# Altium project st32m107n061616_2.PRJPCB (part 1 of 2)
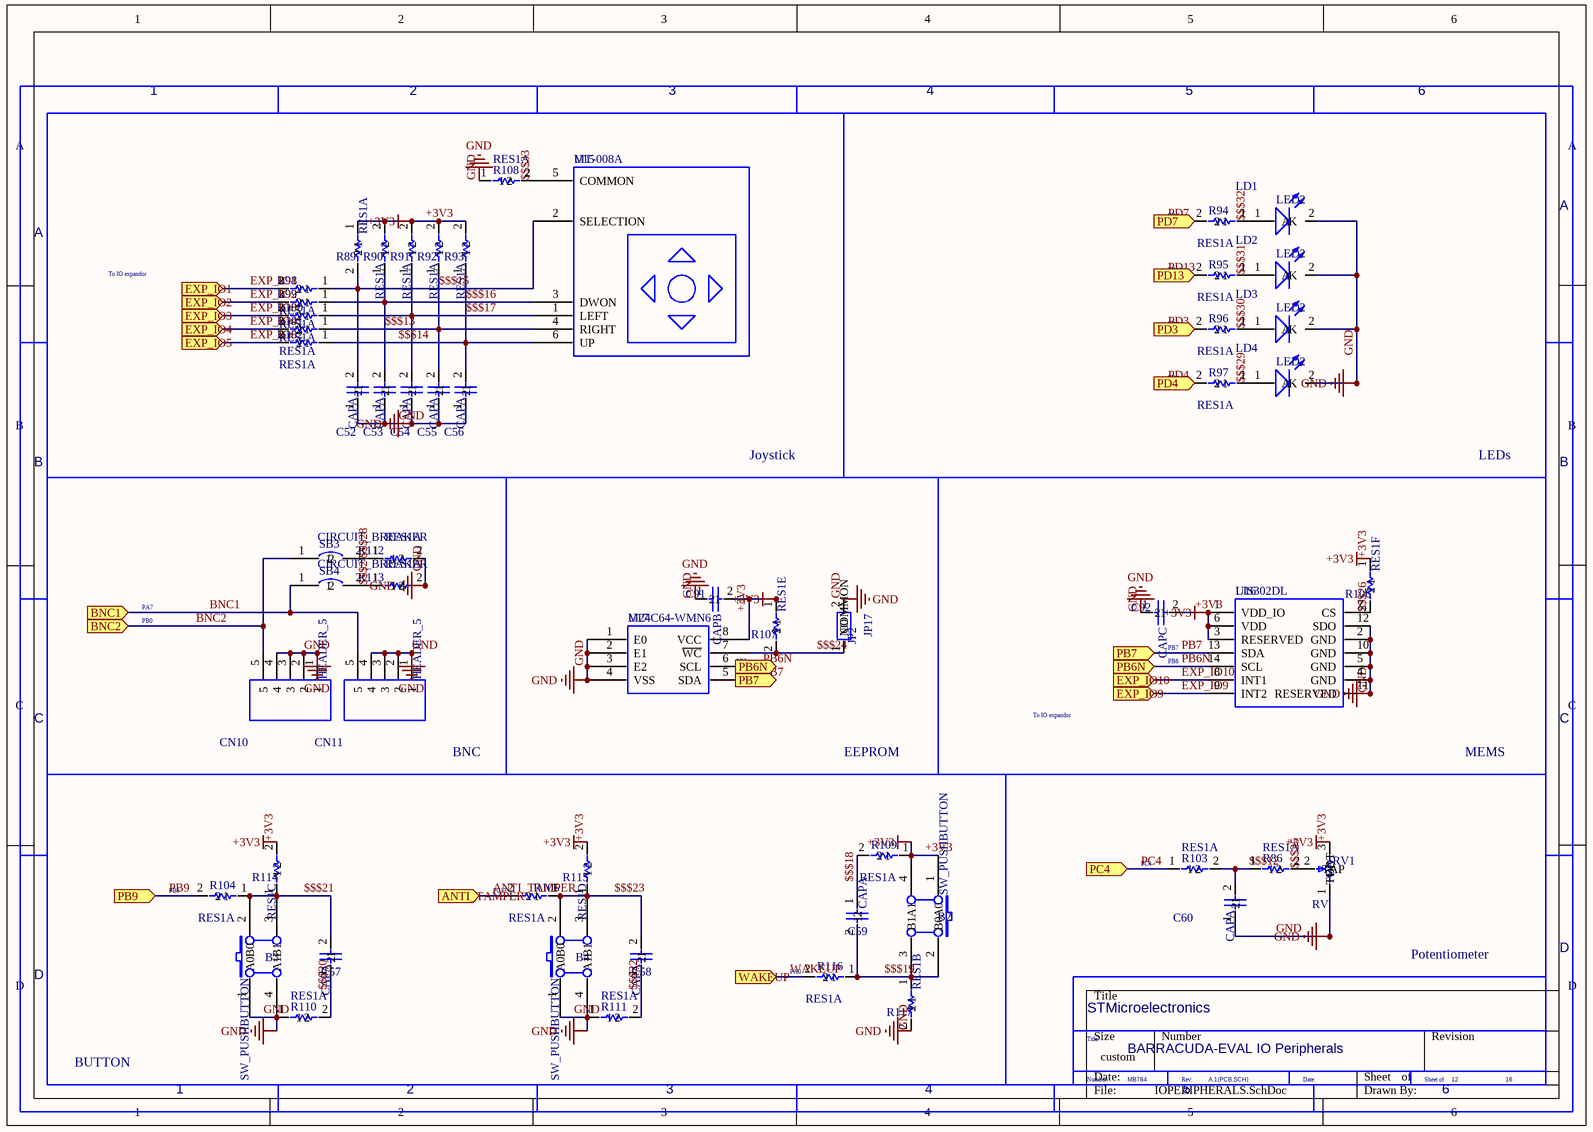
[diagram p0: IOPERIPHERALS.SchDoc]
17 sheets, 434 parts. Net scope: flat (ports and power ports of the same name join across sheets).
Sheets:
  IOPERIPHERALS.SchDoc
  EXTENSIONCONNECTOR.SchDoc
  IO_EXPANDOR.SchDoc
  JTAG&TRACE.SchDoc
  LCD.SchDoc
  MB784.SchDoc
  MCU.SchDoc
  MICROSDCARD.SchDoc
  MOTORCONTROL.SchDoc
  POWER.SchDoc
  SMARTCARD.SchDoc
  USART&IRDA.SchDoc
  USB_OTG_FS.SchDoc
  AUDIO.SchDoc
  CAN.SchDoc
  ETHERNET.SchDoc
  WIFIZGMD.SchDoc

## Sheet IOPERIPHERALS.SchDoc
size 297 x 210 mm

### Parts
B2  SW_PUSHBUTTON
B3  SW_PUSHBUTTON
B4  SW_PUSHBUTTON
C52  CAPA
C53  CAPA
C54  CAPA
C55  CAPA
C56  CAPA
C57  CAPA
C58  CAPA
C59  CAPA
C60  CAPA
C91  CAPB
C92  CAPC
CN10  HEADER_5
CN11  HEADER_5
JP17  JP2
LD1  LED2
LD2  LED2
LD3  LED2
LD4  LED2
R86  RES1A
R89  RES1A
R90  RES1A
R91  RES1A
R92  RES1A
R93  RES1A
R94  RES1A
R95  RES1A
R96  RES1A
R97  RES1A
R98  RES1A
R99  RES1A
R100  RES1A
R101  RES1A
R102  RES1A
R103  RES1A
R104  RES1A
R105  RES1A
R106  RES1F
R107  RES1E
R108  RES1A
R109  RES1A
R110  RES1A
R111  RES1A
R112  RES1A
R113  RES1A
R114  RES1C
R115  RES1D
R116  RES1A
R117  RES1B
RV1  RV
SB3  CIRCUIT_BREAKER
SB4  CIRCUIT_BREAKER
U15  MT-008A
U16  LIS302DL
U17  M24C64-WMN6

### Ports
ANTI_TAMPER, BNC1, BNC2, EXP_IO1, EXP_IO2, EXP_IO3, EXP_IO4, EXP_IO5, EXP_IO9, EXP_IO10, PB6N, PB7, PB9, PC4, PD3, PD4, PD7, PD13, WAKEUP

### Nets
+3V3: B2.1(A0) B2.4(A1) C91.2 C92.2 R89.1 R90.2 R91.2 R92.2 R93.2 R106.1 R107.1 R109.1 R114.2 R115.2 RV1.3(TOP) U16.1(VDD_IO) U16.3(RESERVED) U16.6(VDD) U17.8(VCC)
GND: B3.1(A0) B3.4(A1) B4.1(A0) B4.4(A1) C52.1 C53.1 C54.1 C55.1 C56.1 C60.1 C91.1 C92.1 CN10.1 CN10.2 CN10.3 CN10.4 CN11.1 CN11.2 CN11.3 CN11.4 JP17.2(NO) LD1.2(K) LD2.2(K) LD3.2(K) LD4.2(K) R108.1 R110.1 R111.1 R112.2 R113.2 R117.2 RV1.1(BOT) U16.2(GND) U16.4(GND) U16.5(GND) U16.10(GND) U16.11(RESERVED) U16.12(SDO) U17.1(E0) U17.2(E1) U17.3(E2) U17.4(VSS)  [project net $$$275]
$$$12: C60.2 R86.1 R103.2
$$$13: C52.2 C53.2 C54.2 C55.2 C56.2 R89.2 R90.1 R91.1 R92.1 R93.1 R98.1 R99.1 R100.1 R101.1 R102.1 U15.1(LEFT) U15.2(SELECTION) U15.3(DWON) U15.4(RIGHT) U15.6(UP)  [also labelled $$$14, $$$15, $$$16, $$$17]
$$$18: C59.1 R109.2
$$$19: B2.2(B0) B2.3(B1) C59.2 R116.1 R117.1
$$$20: C57.1 R110.2
$$$21: B3.2(B0) B3.3(B1) C57.2 R104.1 R114.1
$$$22: C58.1 R111.2
$$$23: B4.2(B0) B4.3(B1) C58.2 R105.1 R115.1
$$$24: JP17.1(COMMON) R107.2 U17.7(~{WC})
$$$25: R86.2 RV1.2(TAP)
$$$26: R106.2 U16.7(CS)
$$$27: R113.1 SB4.2
$$$28: R112.1 SB3.2
$$$29: LD4.1(A) R97.1
$$$30: LD3.1(A) R96.1
$$$31: LD2.1(A) R95.1
$$$32: LD1.1(A) R94.1
$$$33: R108.2 U15.5(COMMON)
ANTI_TAMPER: R105.2 ; port ANTI_TAMPER
BNC1: CN10.5 CN11.5 SB3.1 SB4.1 ; port BNC2, port BNC1  [also labelled BNC2]
EXP_IO1: R98.2 ; port EXP_IO1
EXP_IO2: R99.2 ; port EXP_IO2
EXP_IO3: R100.2 ; port EXP_IO3
EXP_IO4: R101.2 ; port EXP_IO4
EXP_IO5: R102.2 ; port EXP_IO5
EXP_IO9: U16.9(INT2) ; port EXP_IO9
EXP_IO10: U16.8(INT1) ; port EXP_IO10
PB6N: U16.14(SCL) U17.6(SCL) ; port PB6N
PB7: U16.13(SDA) U17.5(SDA) ; port PB7
PB9: R104.2 ; port PB9  [project net PB11]
PC4: R103.1 ; port PC4
PD3: R96.2 ; port PD3
PD4: R97.2 ; port PD4
PD7: R94.2 ; port PD7
PD13: R95.2 ; port PD13
WAKEUP: R116.2 ; port WAKEUP

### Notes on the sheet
- 1
- 2
- 3
- 4
- 5
- 6
- A
- To IO expandor
- (near R95) PD13
- (near R94) PD7
- (near R96) PD3
- (near R97) PD4
- B
- Joystick
- LEDs
- PA7
- PB0
- (near U17) PB7
- PB6
- (near C92) PB7
- C
- BNC
- EEPROM
- MEMS
- (near R103) PC4
- (near R104) PB9
- (near R105) PC13
- D
- (near R116) PA0
- STMicroelectronics
- Potentiometer
- BUTTON
- Number:
- Title:
- BARRACUDA-EVAL IO Peripherals
- MB784
- Rev:
- A.1(PCB.SCH)
- Date:
- Sheet of
- 12
- 16

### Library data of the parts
B2-B4 = SW_PUSHBUTTON: SE PUSHBUTTON; PCB DECAL: PB10
C52-C60 = CAPA: Capacitor; Value: 100pF; PCB DECAL: RAD-0.3
C91 = CAPB: Capacitor; PCB DECAL: 0603
C92 = CAPC: Capacitor; PCB DECAL: 0603
CN10 CN11 = HEADER_5: Header, 5-Pin; PCB DECAL: VB334
JP17 = JP2: PCB DECAL: SIP2
LD1-LD4 = LED2: Typical RED, GREEN, YELLOW, AMBER GaAs LED; PCB DECAL: D0603
R86 R89-R105 R108-R113 R116 = RES1A: Resistor; Value: 1K; PCB DECAL: AXIAL-0.3
R106 = RES1F: Resistor; Value: 1K; PCB DECAL: AXIAL-0.3
R107 = RES1E: Resistor; Value: 1K; PCB DECAL: AXIAL-0.3
R114 = RES1C: Resistor; Value: 1K; PCB DECAL: AXIAL-0.3
R115 = RES1D: Resistor; Value: 1K; PCB DECAL: AXIAL-0.3
R117 = RES1B: Resistor; Value: 1K; PCB DECAL: AXIAL-0.3
RV1 = RV: PCB DECAL: ADJRH
SB3 SB4 = CIRCUIT_BREAKER: Circuit Breaker; PCB DECAL: SPST-2
U15 = MT-008A: PCB DECAL: JOY
U17 = M24C64-WMN6: PCB DECAL: SO8

## Sheet EXTENSIONCONNECTOR.SchDoc
size 297 x 210 mm
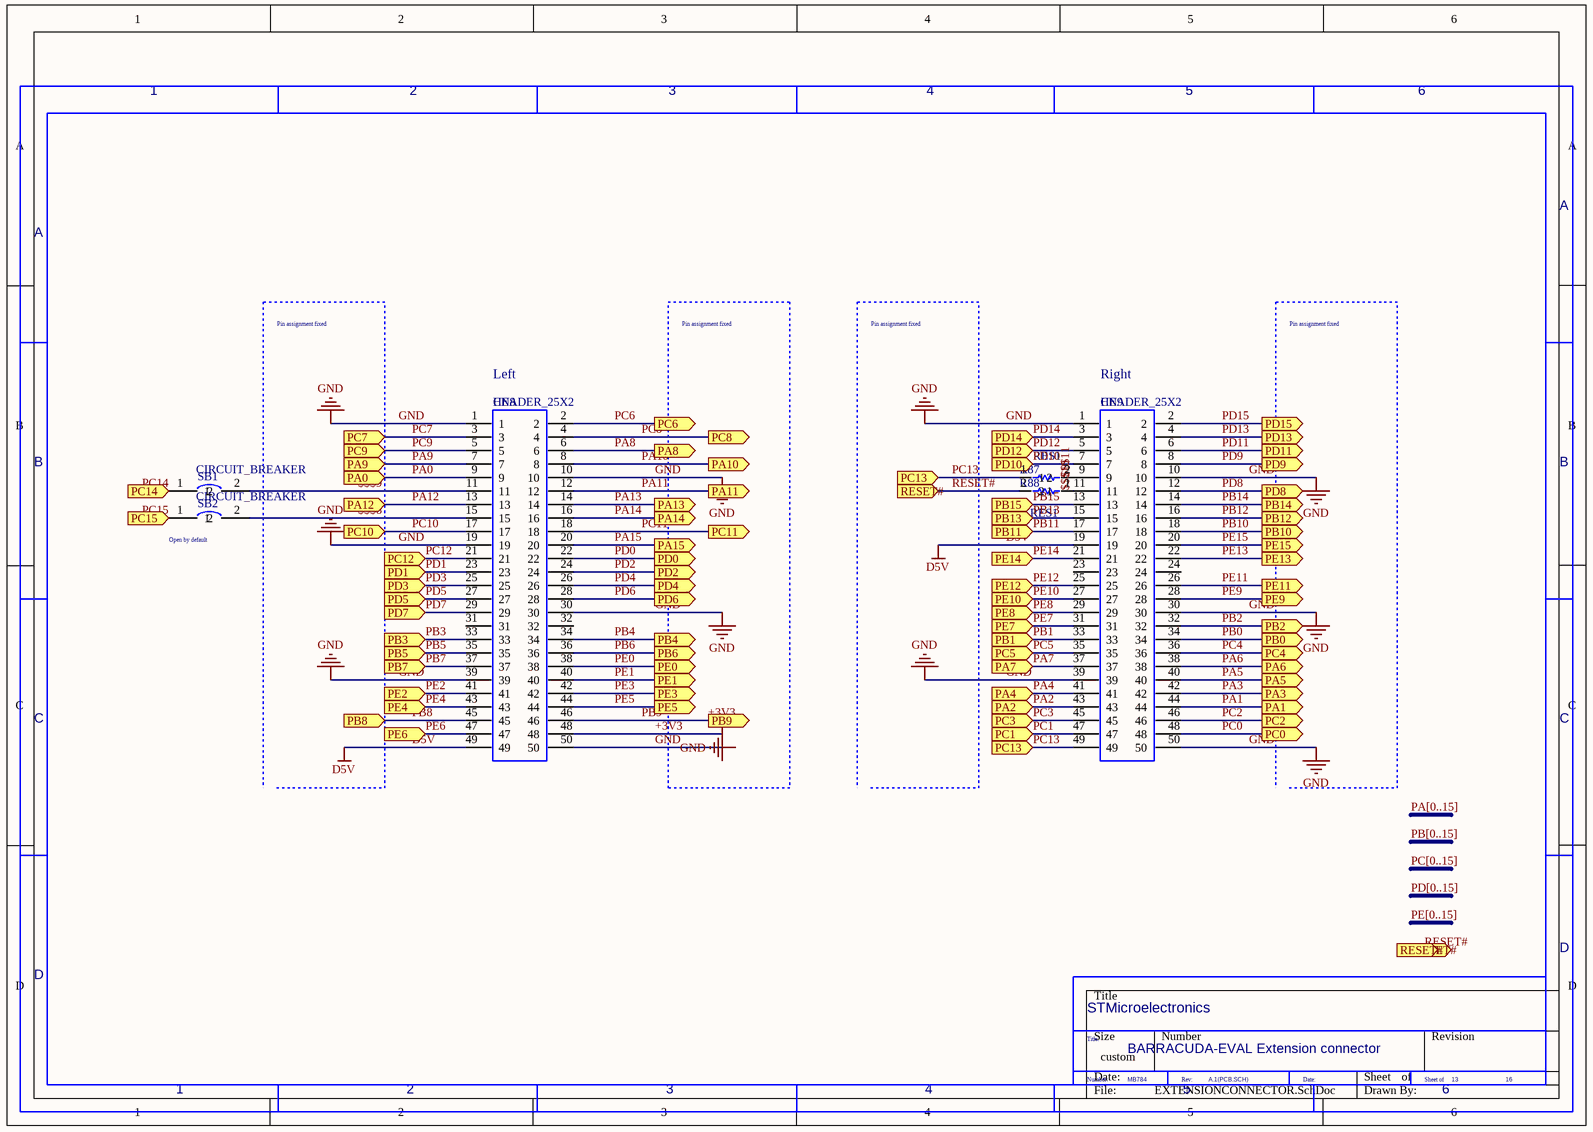
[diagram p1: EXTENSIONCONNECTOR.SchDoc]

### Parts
CN8  HEADER_25X2
CN9  HEADER_25X2
R87  RES1
R88  RES1
SB1  CIRCUIT_BREAKER
SB2  CIRCUIT_BREAKER

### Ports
PA0, PA1, PA2, PA3, PA4, PA5, PA6, PA7, PA8, PA9, PA10, PA11, PA12, PA13, PA14, PA15, PB0, PB1, PB2, PB3, PB4, PB5, PB6, PB7, PB8, PB9, PB10, PB11, PB12, PB13, PB14, PB15, PC0, PC1, PC2, PC3, PC4, PC5, PC6, PC7, PC8, PC9, PC10, PC11, PC12, PC13, PC14, PC15, PD0, PD1, PD2, PD3, PD4, PD5, PD6, PD7, PD8, PD9, PD10, PD11, PD12, PD13, PD14, PD15, PE0, PE1, PE2, PE3, PE4, PE5, PE6, PE7, PE8, PE9, PE10, PE11, PE12, PE13, PE14, PE15, RESET#

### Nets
+3V3: CN8.48
D5V: CN8.49 CN9.19
GND: CN8.1 CN8.10 CN8.13 CN8.14 CN8.19 CN8.30 CN8.39 CN8.50 CN9.1 CN9.10 CN9.30 CN9.39 CN9.50 ; port PA12, port PA13  [also labelled PA12, PA13]  [project net $$$275]
$$$8: CN8.15 SB2.2
$$$9: CN8.11 SB1.2
$$$10: CN9.11 R88.1
$$$11: CN9.9 R87.2
PA0: CN8.9 ; port PA0
PA1: CN9.44 ; port PA1
PA2: CN9.43 ; port PA2
PA3: CN9.42 ; port PA3
PA4: CN9.41 ; port PA4
PA5: CN9.40 ; port PA5
PA6: CN9.38 ; port PA6
PA7: CN9.37 ; port PA7
PA8: CN8.6 ; port PA8
PA9: CN8.7 ; port PA9
PA10: CN8.8 ; port PA10
PA11: CN8.12 ; port PA11
PA14: CN8.16 ; port PA14
PA15: CN8.20 ; port PA15
PB0: CN9.34 ; port PB0
PB1: CN9.33 ; port PB1
PB2: CN9.32 ; port PB2
PB3: CN8.33 ; port PB3
PB4: CN8.34 ; port PB4
PB6: CN8.36 ; port PB6
PB7: CN8.37 ; port PB7
PB8: CN8.45 ; port PB8
PB10: CN9.18 ; port PB10
PB11: CN8.35 CN8.46 CN9.17 ; port PB11, port PB5, port PB9  [also labelled PB5, PB9]
PB12: CN9.16 ; port PB12
PB13: CN9.15 ; port PB13
PB14: CN9.14 ; port PB14
PB15: CN9.13 ; port PB15
PC0: CN9.48 ; port PC0
PC1: CN9.47 ; port PC1
PC2: CN9.46 ; port PC2
PC3: CN9.45 ; port PC3
PC4: CN9.36 ; port PC4
PC5: CN9.35 ; port PC5
PC6: CN8.2 ; port PC6
PC7: CN8.3 ; port PC7
PC8: CN8.4 ; port PC8
PC9: CN8.5 ; port PC9
PC10: CN8.17 ; port PC10  [project net $$$17347]
PC11: CN8.18 ; port PC11
PC12: CN8.21 ; port PC12
PC13: CN9.49 R87.1 ; port PC13
PC14: SB1.1 ; port PC14
PC15: SB2.1 ; port PC15
PD0: CN8.22 ; port PD0
PD1: CN8.23 ; port PD1
PD2: CN8.24 ; port PD2  [project net BNC1]
PD3: CN8.25 ; port PD3
PD4: CN8.26 ; port PD4
PD5: CN8.27 ; port PD5
PD6: CN8.28 ; port PD6
PD7: CN8.29 ; port PD7
PD8: CN9.12 ; port PD8
PD9: CN9.8 ; port PD9
PD10: CN9.7 ; port PD10
PD11: CN9.6 ; port PD11
PD12: CN9.5 ; port PD12
PD13: CN9.4 ; port PD13
PD14: CN9.3 ; port PD14
PD15: CN9.2 ; port PD15
PE0: CN8.38 ; port PE0
PE1: CN8.40 ; port PE1
PE2: CN8.41 ; port PE2
PE3: CN8.42 ; port PE3
PE4: CN8.43 ; port PE4
PE5: CN8.44 ; port PE5
PE6: CN8.47 ; port PE6
PE7: CN9.31 ; port PE7
PE8: CN9.29 ; port PE8
PE9: CN9.28 ; port PE9
PE10: CN9.27 ; port PE10
PE11: CN9.26 ; port PE11
PE12: CN9.25 ; port PE12
PE13: CN9.22 ; port PE13
PE14: CN9.21 ; port PE14
PE15: CN9.20 ; port PE15
RESET#: R88.2 ; port RESET#

Not connected (* = marked no-connect by the designer): CN8 31 32; CN9 23 24

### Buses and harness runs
bus PA[0..15]
bus PB[0..15]
bus PC[0..15]
bus PD[0..15]
bus PE[0..15]

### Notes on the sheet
- 1
- 2
- 3
- 4
- 5
- 6
- A
- Pin assignment fixed
- (near CN8) Left
- (near CN9) Right
- B
- (near SB2) Open by default
- C
- D
- STMicroelectronics
- Number:
- Title:
- BARRACUDA-EVAL Extension connector
- MB784
- Rev:
- A.1(PCB.SCH)
- Date:
- Sheet of
- 13
- 16

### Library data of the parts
CN8 CN9 = HEADER_25X2: Header, 25-Pin, Dual row; PCB DECAL: 2*25P
R87 R88 = RES1: Resistor; Value: 1K; PCB DECAL: AXIAL-0.3
SB1 SB2 = CIRCUIT_BREAKER: Circuit Breaker; PCB DECAL: SPST-2

## Sheet IO_EXPANDOR.SchDoc
size 297 x 210 mm
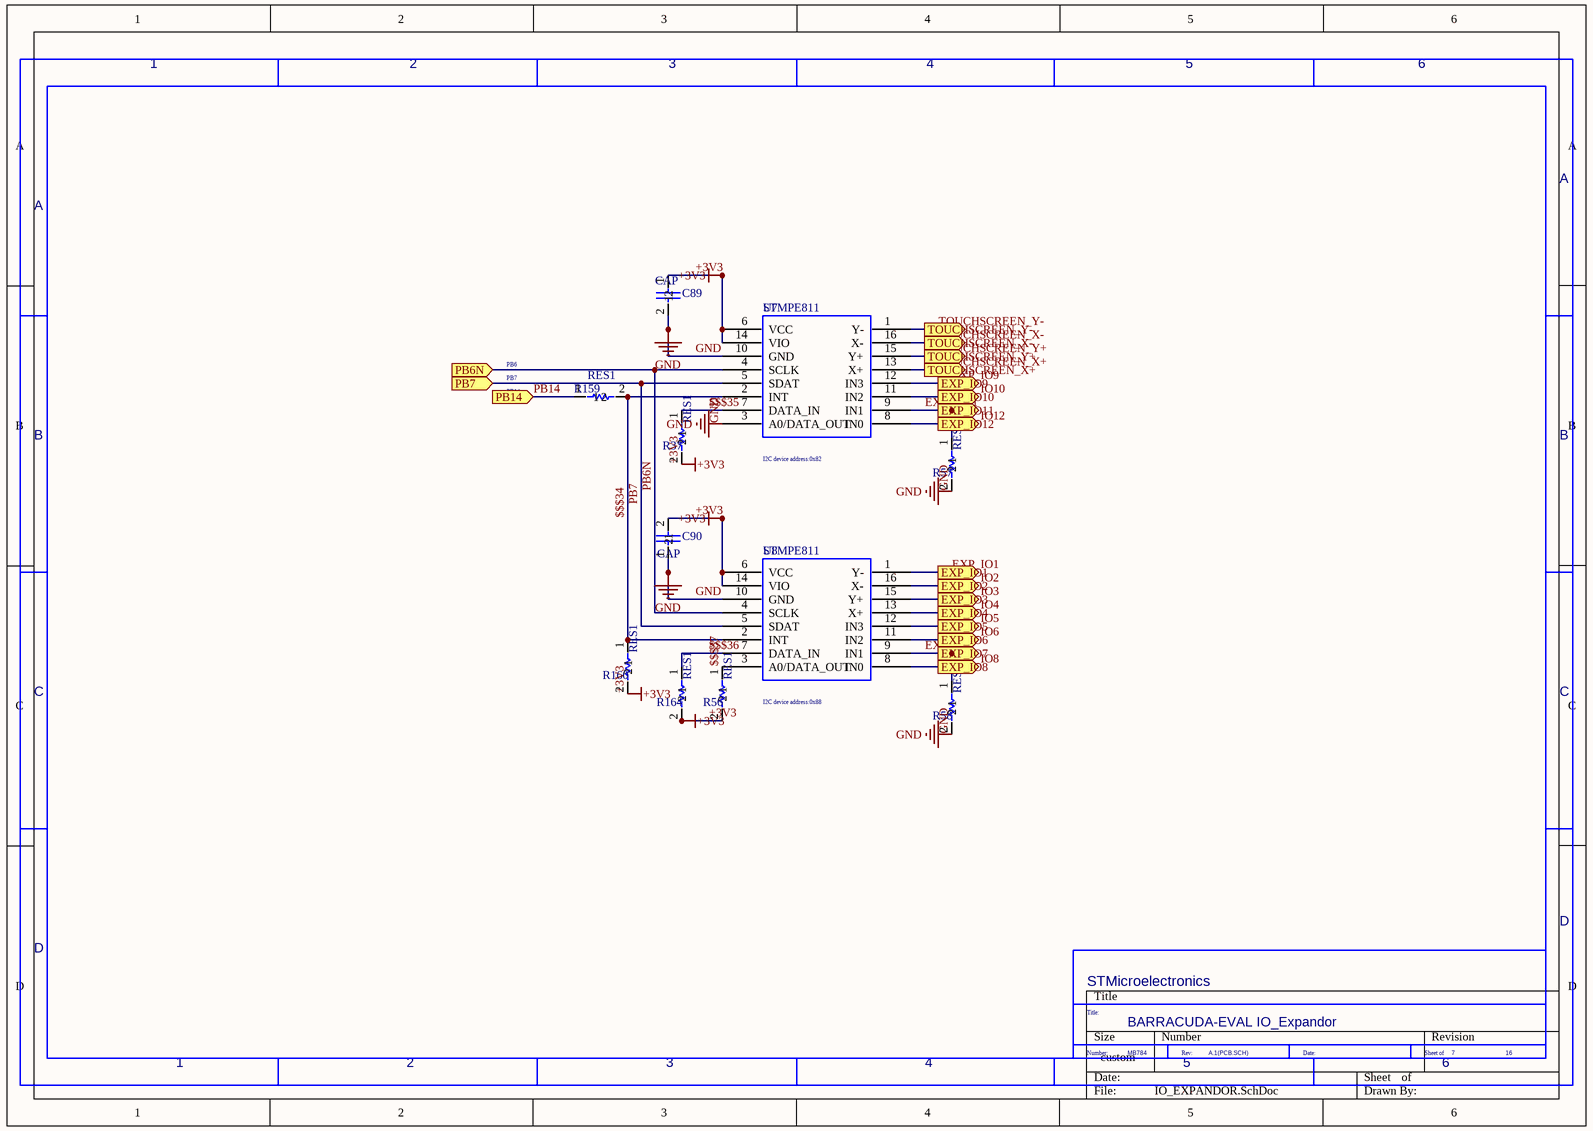
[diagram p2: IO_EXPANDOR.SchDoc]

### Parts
C89  CAP
C90  CAP
R37  RES1
R56  RES1
R57  RES1
R58  RES1
R159  RES1
R160  RES1
R164  RES1
U7  STMPE811
U8  STMPE811

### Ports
EXP_IO1, EXP_IO2, EXP_IO3, EXP_IO4, EXP_IO5, EXP_IO6, EXP_IO7, EXP_IO8, EXP_IO9, EXP_IO10, EXP_IO11, EXP_IO12, PB6N, PB7, PB14, TOUCHSCREEN_X+, TOUCHSCREEN_X-, TOUCHSCREEN_Y+, TOUCHSCREEN_Y-

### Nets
+3V3: C89.1 C90.2 R37.2 R56.2 R160.2 R164.2 U7.6(VCC) U7.14(VIO) U8.6(VCC) U8.14(VIO)
GND: C89.2 C90.1 R57.2 R58.2 U7.3(A0/DATA_OUT) U7.10(GND) U8.10(GND)  [project net $$$275]
$$$34: R159.2 R160.1 U7.2(INT) U8.2(INT)
$$$35: R37.1 U7.7(DATA_IN)
$$$36: R164.1 U8.7(DATA_IN)
$$$37: R56.1 U8.3(A0/DATA_OUT)
EXP_IO1: U8.1(Y-) ; port EXP_IO1
EXP_IO2: U8.16(X-) ; port EXP_IO2
EXP_IO3: U8.15(Y+) ; port EXP_IO3
EXP_IO4: U8.13(X+) ; port EXP_IO4
EXP_IO5: U8.12(IN3) ; port EXP_IO5
EXP_IO6: U8.11(IN2) ; port EXP_IO6
EXP_IO7: R58.1 U8.8(IN0) U8.9(IN1) ; port EXP_IO8, port EXP_IO7  [also labelled EXP_IO8]
EXP_IO9: U7.12(IN3) ; port EXP_IO9
EXP_IO10: U7.11(IN2) ; port EXP_IO10
EXP_IO11: R57.1 U7.8(IN0) U7.9(IN1) ; port EXP_IO12, port EXP_IO11  [also labelled EXP_IO12]
PB6N: U7.4(SCLK) U8.4(SCLK) ; port PB6N
PB7: U7.5(SDAT) U8.5(SDAT) ; port PB7
PB14: R159.1 ; port PB14
TOUCHSCREEN_X+: U7.13(X+) ; port TOUCHSCREEN_X+
TOUCHSCREEN_X-: U7.16(X-) ; port TOUCHSCREEN_X-
TOUCHSCREEN_Y+: U7.15(Y+) ; port TOUCHSCREEN_Y+
TOUCHSCREEN_Y-: U7.1(Y-) ; port TOUCHSCREEN_Y-

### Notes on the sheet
- 1
- 2
- 3
- 4
- 5
- 6
- A
- PB14
- PB7
- PB6
- B
- (near U7) I2C device address:0x82
- C
- I2C device address:0x88
- D
- Title:
- STMicroelectronics
- Number:
- BARRACUDA-EVAL IO_Expandor
- MB784
- Rev:
- A.1(PCB.SCH)
- Date:
- Sheet of
- 7
- 16

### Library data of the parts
C89 C90 = CAP: Capacitor; PCB DECAL: 0603
R37 R56-R58 R159 R160 R164 = RES1: as R87 on sheet EXTENSIONCONNECTOR
U7 U8 = STMPE811: PCB DECAL: QFN16

## Sheet JTAG&TRACE.SchDoc
size 297 x 210 mm
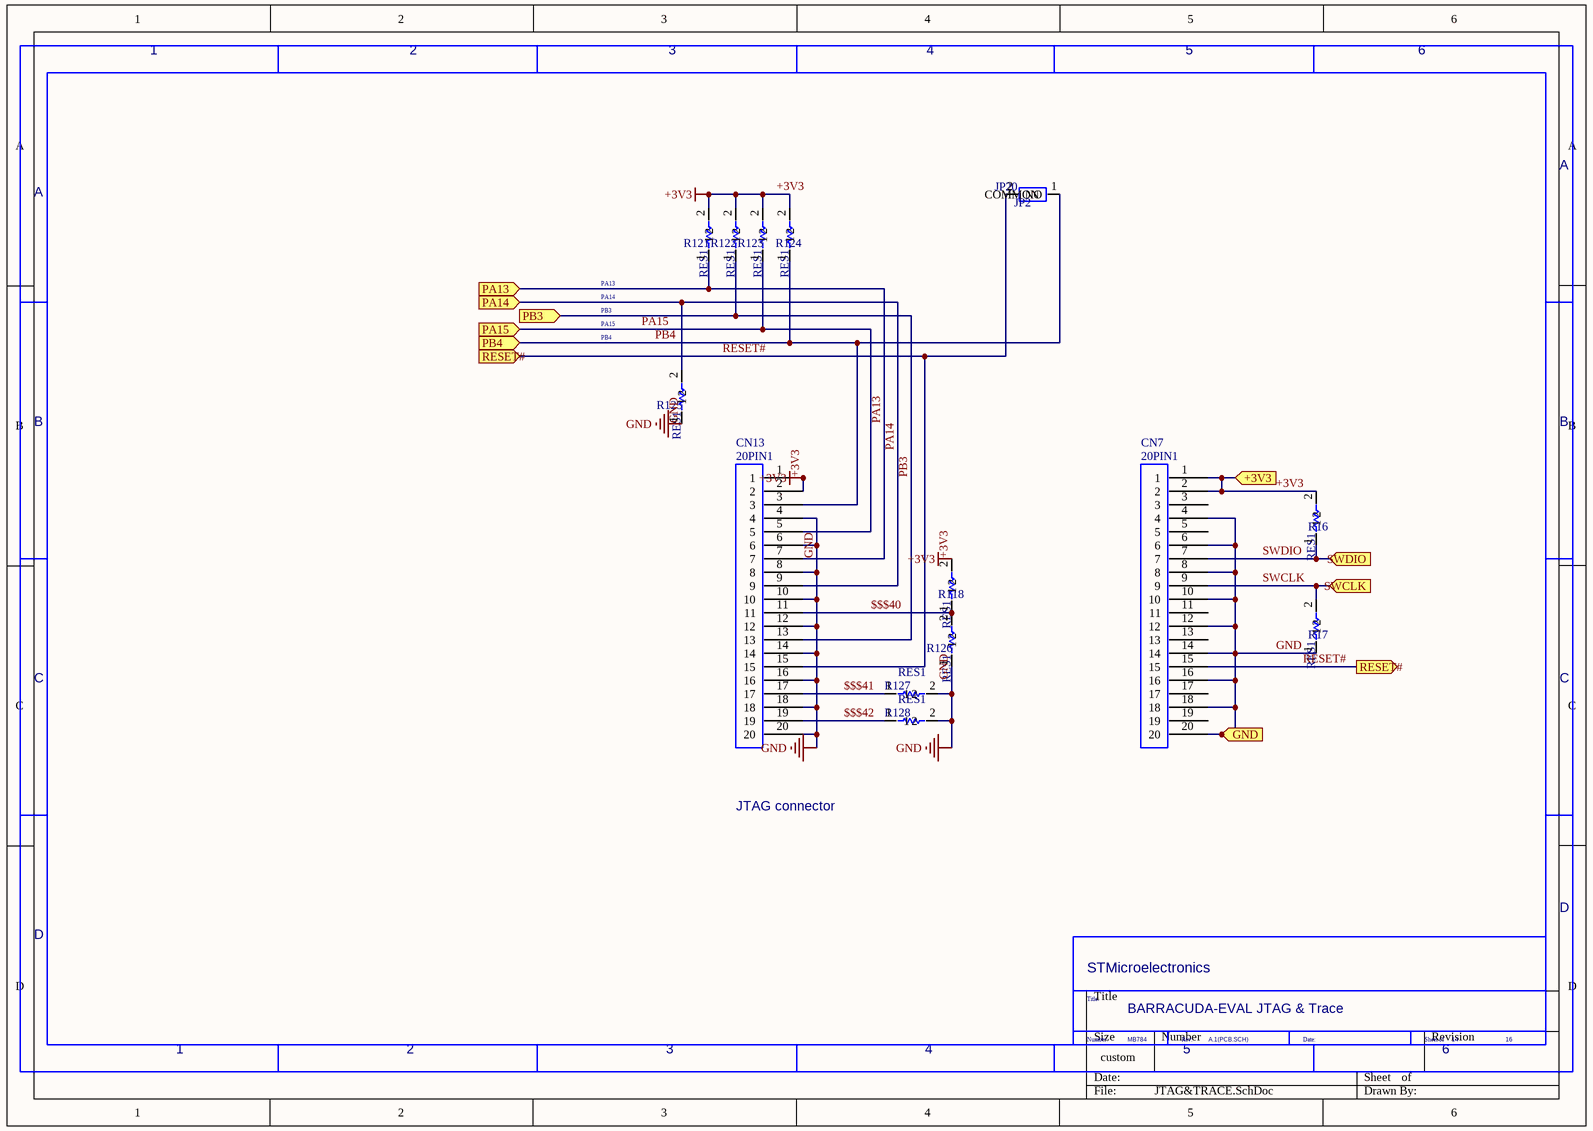
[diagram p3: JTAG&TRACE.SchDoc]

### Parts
CN7  20PIN1
CN13  20PIN1
JP20  JP2
R16  RES1
R17  RES1
R118  RES1
R121  RES1
R122  RES1
R123  RES1
R124  RES1
R125  RES1
R126  RES1
R127  RES1
R128  RES1

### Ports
+3V3, GND, PA13, PA14, PA15, PB3, PB4, RESET#, SWCLK, SWDIO

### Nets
+3V3: CN7.1 CN7.2 CN13.1 CN13.2 R16.2 R118.2 R121.2 R122.2 R123.2 R124.2 ; port +3V3
GND: CN7.4 CN7.6 CN7.8 CN7.10 CN7.12 CN7.14 CN7.16 CN7.18 CN7.20 CN13.4 CN13.6 CN13.7 CN13.8 CN13.10 CN13.12 CN13.14 CN13.16 CN13.18 CN13.20 R17.1 R121.1 R125.1 R126.1 R127.2 R128.2 ; port PA13, port GND  [also labelled PA13]  [project net $$$275]
$$$40: CN13.11 R118.1 R126.2
$$$41: CN13.17 R127.1
$$$42: CN13.19 R128.1
PA14: CN13.9 R125.2 ; port PA14
PA15: CN13.5 R123.1 ; port PA15
PB3: CN13.13 R122.1 ; port PB3
PB4: CN13.3 JP20.1(COMMON) R124.1 ; port PB4
RESET#: CN7.15 CN13.15 JP20.2(NO) ; port RESET#
SWCLK: CN7.9 R17.2 ; port SWCLK
SWDIO: CN7.7 R16.1 ; port SWDIO

Not connected (* = marked no-connect by the designer): CN7 3 5 11 13 17 19

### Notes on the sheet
- 1
- 2
- 3
- 4
- 5
- 6
- A
- PB4
- PA15
- PB3
- PA14
- PA13
- B
- C
- JTAG connector
- D
- Title:
- STMicroelectronics
- BARRACUDA-EVAL JTAG & Trace
- Number:
- MB784
- Rev:
- A.1(PCB.SCH)
- Date:
- Sheet of
- 14
- 16

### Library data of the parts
CN7 CN13 = 20PIN1: PCB DECAL: IDC20S
JP20 = JP2: PCB DECAL: SIP2
R16 R17 = RES1: Resistor; Value: 10K; PCB DECAL: AXIAL-0.3
R118 R121-R128 = RES1: as R87 on sheet EXTENSIONCONNECTOR

## Sheet LCD.SchDoc
size 297 x 210 mm
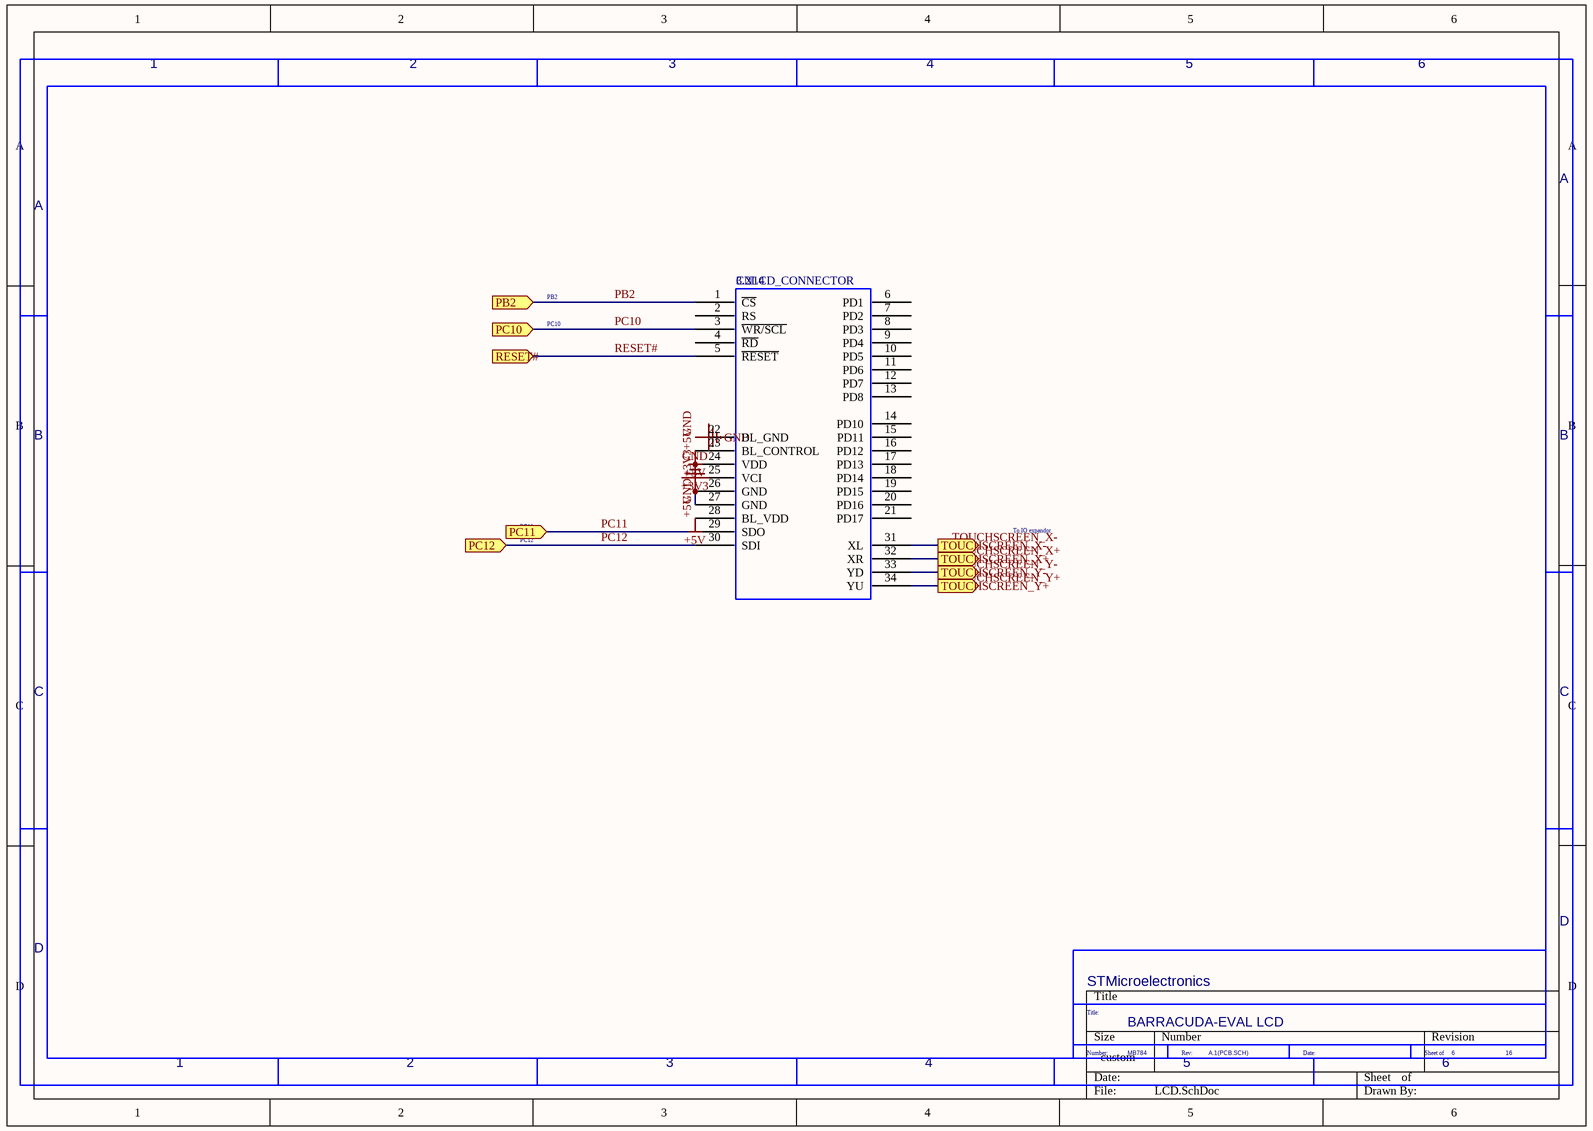
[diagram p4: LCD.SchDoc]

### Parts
CN14  3.2LCD_CONNECTOR

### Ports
PB2, PC10, PC11, PC12, RESET#, TOUCHSCREEN_X+, TOUCHSCREEN_X-, TOUCHSCREEN_Y+, TOUCHSCREEN_Y-

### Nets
+3V3: CN14.24(VDD) CN14.25(VCI)
+5V: CN14.23(BL_CONTROL) CN14.28(BL_VDD)
GND: CN14.22(BL_GND) CN14.26(GND) CN14.27(GND)  [project net $$$275]
PB2: CN14.1(~{CS}) ; port PB2
PC10: CN14.3(~{WR/SCL}) ; port PC10  [project net $$$17347]
PC11: CN14.29(SDO) ; port PC11
PC12: CN14.30(SDI) ; port PC12
RESET#: CN14.5(~{RESET}) ; port RESET#
TOUCHSCREEN_X+: CN14.32(XR) ; port TOUCHSCREEN_X+
TOUCHSCREEN_X-: CN14.31(XL) ; port TOUCHSCREEN_X-
TOUCHSCREEN_Y+: CN14.34(YU) ; port TOUCHSCREEN_Y+
TOUCHSCREEN_Y-: CN14.33(YD) ; port TOUCHSCREEN_Y-

Not connected (* = marked no-connect by the designer): CN14 2(RS) 4(~{RD}) 6(PD1) 7(PD2) 8(PD3) 9(PD4) 10(PD5) 11(PD6) 12(PD7) 13(PD8) 14(PD10) 15(PD11) 16(PD12) 17(PD13) 18(PD14) 19(PD15) 20(PD16) 21(PD17)

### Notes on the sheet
- 1
- 2
- 3
- 4
- 5
- 6
- A
- PC10
- PB2
- B
- PC12
- PC11
- To IO expandor
- C
- D
- Title:
- STMicroelectronics
- Number:
- BARRACUDA-EVAL LCD
- MB784
- Rev:
- A.1(PCB.SCH)
- Date:
- Sheet of
- 16

## Sheet MB784.SchDoc
size 297 x 210 mm

## Sheet MCU.SchDoc
size 297 x 210 mm
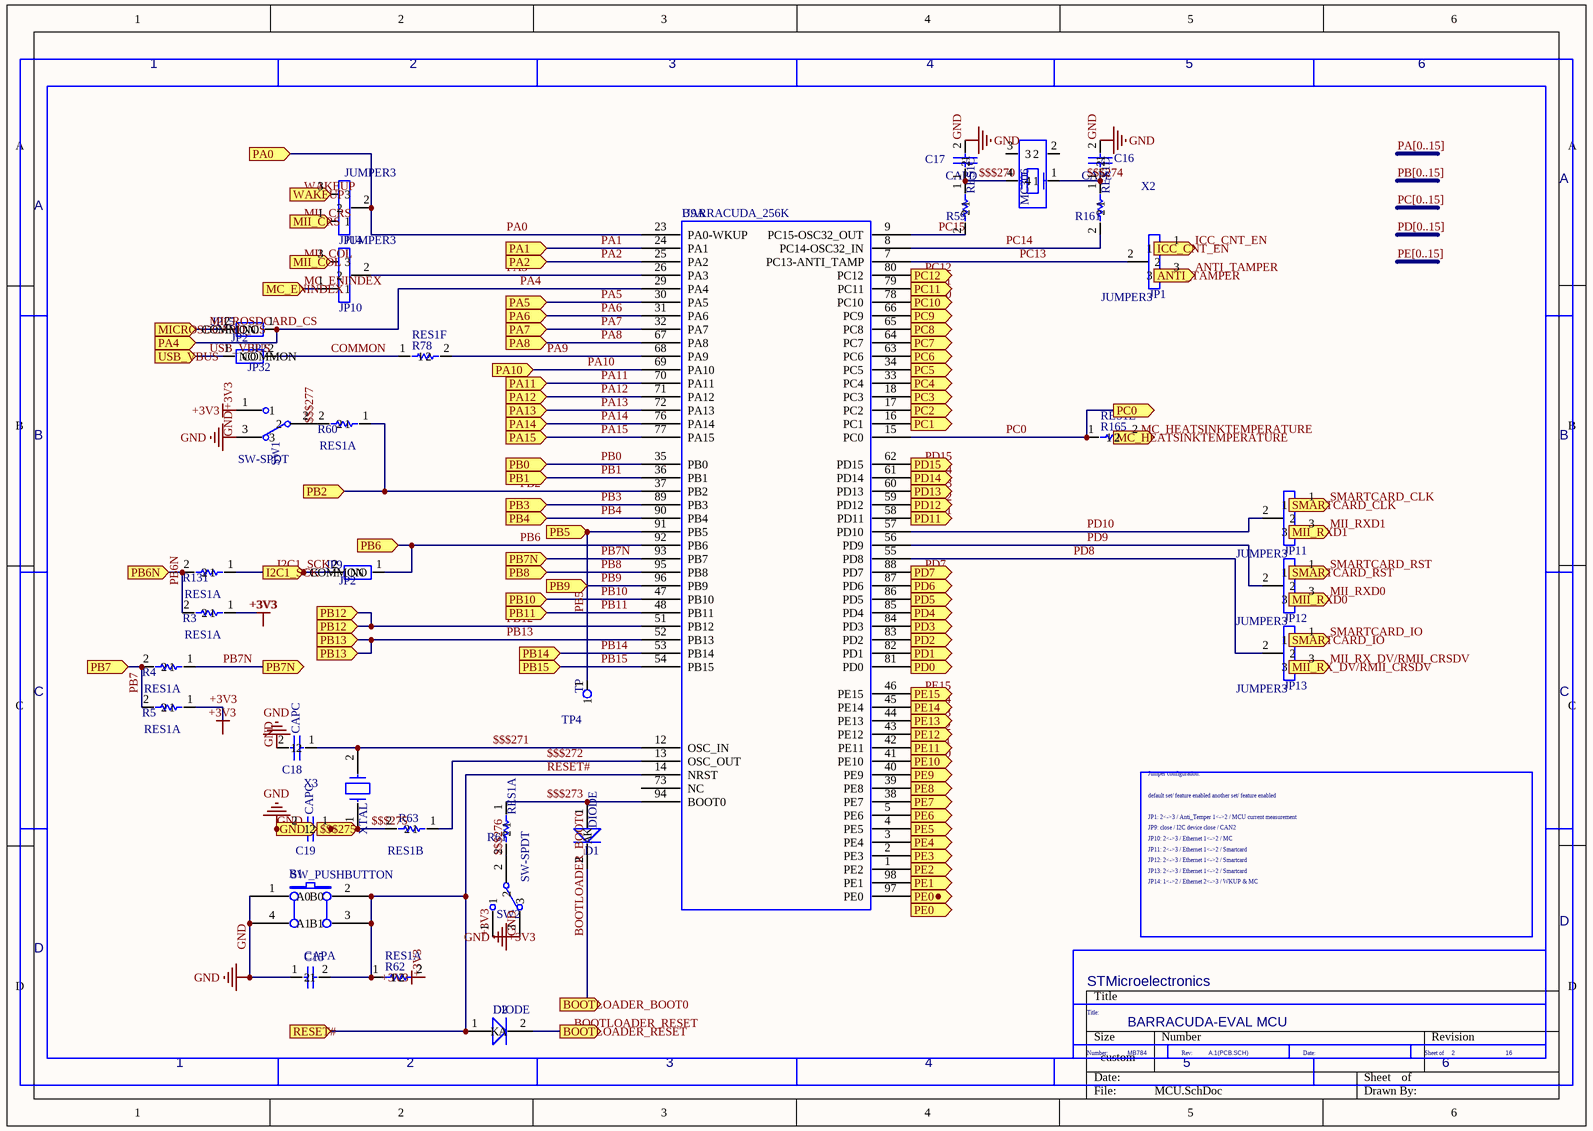
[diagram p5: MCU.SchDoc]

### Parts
B1  SW_PUSHBUTTON
C15  CAPA
C16  CAPE
C17  CAPD
C18  CAPC
C19  CAPC
D1  DIODE
D2  DIODE
JP1  JUMPER3
JP9  JP2
JP10  JUMPER3
JP11  JUMPER3
JP12  JUMPER3
JP13  JUMPER3
JP14  JUMPER3
JP15  JP2
JP32  JP2
R3  RES1A
R4  RES1A
R5  RES1A
R59  RES1C
R60  RES1A
R61  RES1A
R62  RES1A
R63  RES1B
R78  RES1F
R131  RES1A
R161  RES1D
R165  RES1E
SW1  SW-SPDT
SW2  SW-SPDT
TP4  TP
U9  BARRACUDA_256K  (part A of 2)
X2  MC306
X3  XTAL

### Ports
$$$275, ANTI_TAMPER, BOOTLOADER_BOOT0, BOOTLOADER_RESET, GND, I2C1_SCK, ICC_CNT_EN, MC_ENINDEX, MC_HEATSINKTEMPERATURE, MICROSDCARD_CS, MII_COL, MII_CRS, MII_RX_DV/RMII_CRSDV, MII_RXD0, MII_RXD1, PA0, PA1, PA2, PA4, PA5, PA6, PA7, PA8, PA10, PA11, PA12, PA13, PA14, PA15, PB0, PB1, PB2, PB3, PB4, PB5, PB6, PB6N, PB7, PB7N, PB8, PB9, PB10, PB11, PB12, PB13, PB14, PB15, PC0, PC1, PC2, PC3, PC4, PC5, PC6, PC7, PC8, PC9, PC10, PC11, PC12, PD0, PD1, PD2, PD3, PD4, PD5, PD6, PD7, PD11, PD12, PD13, PD14, PD15, PE0, PE1, PE2, PE3, PE4, PE5, PE6, PE7, PE8, PE9, PE10, PE11, PE12, PE13, PE14, PE15, RESET#, SMARTCARD_CLK, SMARTCARD_IO, SMARTCARD_RST, USB_VBUS, WAKEUP

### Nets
$$$275: B1.1(A0) B1.4(A1) C15.1 C16.2 C17.2 C18.2 C19.1 C19.2 R63.2 SW1.3 SW2.3 U9.71(PA12) U9.72(PA13) X3.1 ; port PA13, port PA12, port $$$275, port GND  [also labelled GND, PA12, PA13]
+3V3: R3.1 R5.1 R62.2 SW1.1 SW2.1
$$$270: C17.1 R59.1 X2.4
$$$271: C18.1 U9.12(OSC_IN) X3.2
$$$272: R63.1 U9.13(OSC_OUT)
$$$273: D1.1(A) R61.1 U9.94(BOOT0)
$$$274: C16.1 R161.1 X2.1
$$$276: R61.2 SW2.2
$$$277: R60.2 SW1.2
ANTI_TAMPER: JP1.3 ; port ANTI_TAMPER
BOOTLOADER_BOOT0: D1.2(K) ; port BOOTLOADER_BOOT0
BOOTLOADER_RESET: D2.2(K) ; port BOOTLOADER_RESET
COMMON: JP32.2(NO) R78.1
I2C1_SCK: JP9.2(NO) R131.1 ; port I2C1_SCK
ICC_CNT_EN: JP1.1 ; port ICC_CNT_EN
MC_ENINDEX: JP10.1 ; port MC_ENINDEX
MC_HEATSINKTEMPERATURE: R165.2 ; port MC_HEATSINKTEMPERATURE
MICROSDCARD_CS: JP15.2(NO) ; port MICROSDCARD_CS
MII_COL: JP10.3 ; port MII_COL
MII_CRS: JP14.1 ; port MII_CRS
MII_RX_DV/RMII_CRSDV: JP13.3 ; port MII_RX_DV/RMII_CRSDV
MII_RXD0: JP12.3 ; port MII_RXD0
MII_RXD1: JP11.3 ; port MII_RXD1
PA0: JP14.2 U9.23(PA0-WKUP) ; port PA0
PA1: U9.24(PA1) ; port PA1
PA2: U9.25(PA2) ; port PA2
PA3: JP10.2 U9.26(PA3)
PA4: JP15.1(COMMON) U9.29(PA4) ; port PA4
PA5: U9.30(PA5) ; port PA5
PA6: U9.31(PA6) ; port PA6
PA7: U9.32(PA7) ; port PA7
PA8: U9.67(PA8) ; port PA8
PA9: R78.2 U9.68(PA9)
PA10: U9.69(PA10) ; port PA10
PA11: U9.70(PA11) ; port PA11
PA14: U9.76(PA14) ; port PA14
PA15: U9.77(PA15) ; port PA15
PB0: U9.35(PB0) ; port PB0
PB1: U9.36(PB1) ; port PB1
PB2: R60.1 U9.37(PB2) ; port PB2
PB3: U9.89(PB3) ; port PB3
PB4: U9.90(PB4) ; port PB4
PB6: JP9.1(COMMON) U9.92(PB6) ; port PB6
PB6N: R3.2 R131.2 ; port PB6N
PB7: R4.2 R5.2 ; port PB7
PB7N: R4.1 U9.93(PB7) ; port PB7N
PB8: U9.95(PB8) ; port PB8
PB10: U9.47(PB10) ; port PB10
PB11: TP4.1 U9.48(PB11) U9.91(PB5) U9.96(PB9) ; port PB9, port PB5, port PB11  [also labelled PB5, PB9]
PB12: U9.51(PB12) ; port PB12
PB13: U9.52(PB13) ; port PB13
PB14: U9.53(PB14) ; port PB14
PB15: U9.54(PB15) ; port PB15
PC0: R165.1 U9.15(PC0) ; port PC0
PC1: U9.16(PC1) ; port PC1
PC2: U9.17(PC2) ; port PC2
PC3: U9.18(PC3) ; port PC3
PC4: U9.33(PC4) ; port PC4
PC5: U9.34(PC5) ; port PC5
PC6: U9.63(PC6) ; port PC6
PC7: U9.64(PC7) ; port PC7
PC8: U9.65(PC8) ; port PC8
PC9: U9.66(PC9) ; port PC9
PC10: U9.78(PC10) ; port PC10  [project net $$$17347]
PC11: U9.79(PC11) ; port PC11
PC12: U9.80(PC12) ; port PC12
PC13: JP1.2 U9.7(PC13-ANTI_TAMP)
PC14: R161.2 U9.8(PC14-OSC32_IN)
PC15: R59.2 U9.9(PC15-OSC32_OUT)
PD0: U9.81(PD0) ; port PD0
PD1: U9.82(PD1) ; port PD1
PD2: U9.83(PD2) ; port PD2  [project net BNC1]
PD3: U9.84(PD3) ; port PD3
PD4: U9.85(PD4) ; port PD4
PD5: U9.86(PD5) ; port PD5
PD6: U9.87(PD6) ; port PD6
PD7: U9.88(PD7) ; port PD7
PD8: JP13.2 U9.55(PD8)
PD9: JP12.2 U9.56(PD9)
PD10: JP11.2 U9.57(PD10)
PD11: U9.58(PD11) ; port PD11
PD12: U9.59(PD12) ; port PD12
PD13: U9.60(PD13) ; port PD13
PD14: U9.61(PD14) ; port PD14
PD15: U9.62(PD15) ; port PD15
PE0: U9.97(PE0) ; port PE0
PE1: U9.98(PE1) ; port PE1
PE2: U9.1(PE2) ; port PE2
PE3: U9.2(PE3) ; port PE3
PE4: U9.3(PE4) ; port PE4
PE5: U9.4(PE5) ; port PE5
PE6: U9.5(PE6) ; port PE6
PE7: U9.38(PE7) ; port PE7
PE8: U9.39(PE8) ; port PE8
PE9: U9.40(PE9) ; port PE9
PE10: U9.41(PE10) ; port PE10
PE11: U9.42(PE11) ; port PE11
PE12: U9.43(PE12) ; port PE12
PE13: U9.44(PE13) ; port PE13
PE14: U9.45(PE14) ; port PE14
PE15: U9.46(PE15) ; port PE15
RESET#: B1.2(B0) B1.3(B1) C15.2 D2.1(A) R62.1 U9.14(NRST) ; port RESET#
SMARTCARD_CLK: JP11.1 ; port SMARTCARD_CLK
SMARTCARD_IO: JP13.1 ; port SMARTCARD_IO
SMARTCARD_RST: JP12.1 ; port SMARTCARD_RST
USB_VBUS: JP32.1(COMMON) ; port USB_VBUS
WAKEUP: JP14.3 ; port WAKEUP

Not connected (* = marked no-connect by the designer): U9 73(NC); X2 2 3

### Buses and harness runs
bus PA[0..15]
bus PB[0..15]
bus PC[0..15]
bus PD[0..15]
bus PE[0..15]

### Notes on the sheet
- 1
- 2
- 3
- 4
- 5
- 6
- A
- B
- C
- default set/ feature enabled another set/ feature enabled
- Jumper configuration:
- JP14: 1<->2 / Ethernet 2<->3 / WKUP & MC
- JP13: 2<->3 / Ethernet 1<->2 / Smartcard
- JP12: 2<->3 / Ethernet 1<->2 / Smartcard
- JP11: 2<->3 / Ethernet 1<->2 / Smartcard
- JP10: 2<->3 / Ethernet 1<->2 / MC
- JP9: close / I2C device close / CAN2
- JP1: 2<->3 / Anti_Temper 1<->2 / MCU current measurement
- D
- Title:
- STMicroelectronics
- Number:
- BARRACUDA-EVAL MCU
- MB784
- Rev:
- A.1(PCB.SCH)
- Date:
- Sheet of
- 16

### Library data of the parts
B1 = SW_PUSHBUTTON: SE PUSHBUTTON; PCB DECAL: PB10
C15 = CAPA: Capacitor; Value: 100pF; PCB DECAL: 0603P
C16 = CAPE: Capacitor; PCB DECAL: 0603
C17 = CAPD: Capacitor; PCB DECAL: 0603
C18 C19 = CAPC: Capacitor; PCB DECAL: 0603
D1 D2 = DIODE: Default Diode; Code - JEDEC: DO-214-AB; PCB DECAL: DSO-C2/X3.3
JP1 JP10-JP14 = JUMPER3: PCB DECAL: SIP3
JP9 JP15 JP32 = JP2: PCB DECAL: SIP2
R3 R5 = RES1A: Resistor; Value: 4K7; PCB DECAL: AXIAL-0.3
R4 R131 = RES1A: Resistor; Value: 0; PCB DECAL: AXIAL-0.3
R59 = RES1C: as R114 on sheet IOPERIPHERALS
R60 R61 = RES1A: as R86 on sheet IOPERIPHERALS
R62 = RES1A: Resistor; Value: 1K; PCB DECAL: 0603
R63 = RES1B: as R117 on sheet IOPERIPHERALS
R78 = RES1F: as R106 on sheet IOPERIPHERALS
R161 = RES1D: as R115 on sheet IOPERIPHERALS
R165 = RES1E: as R107 on sheet IOPERIPHERALS
SW1 SW2 = SW-SPDT: SPDT Subminiature Toggle Switch, Right Angle Mounting, Vertical Actuation; Revision 1: Jul-2002: Re-released for DXP Platform.; Revision 2: 17-Dec-2003: Schematic revised, PCB Footprint replaced.; PCB DECAL: SIP3
U9 = BARRACUDA_256K: PCB DECAL: TQFP100
X2 = MC306: PCB DECAL: SM8
X3 = XTAL: Crystal

## Sheet MICROSDCARD.SchDoc
size 297 x 210 mm
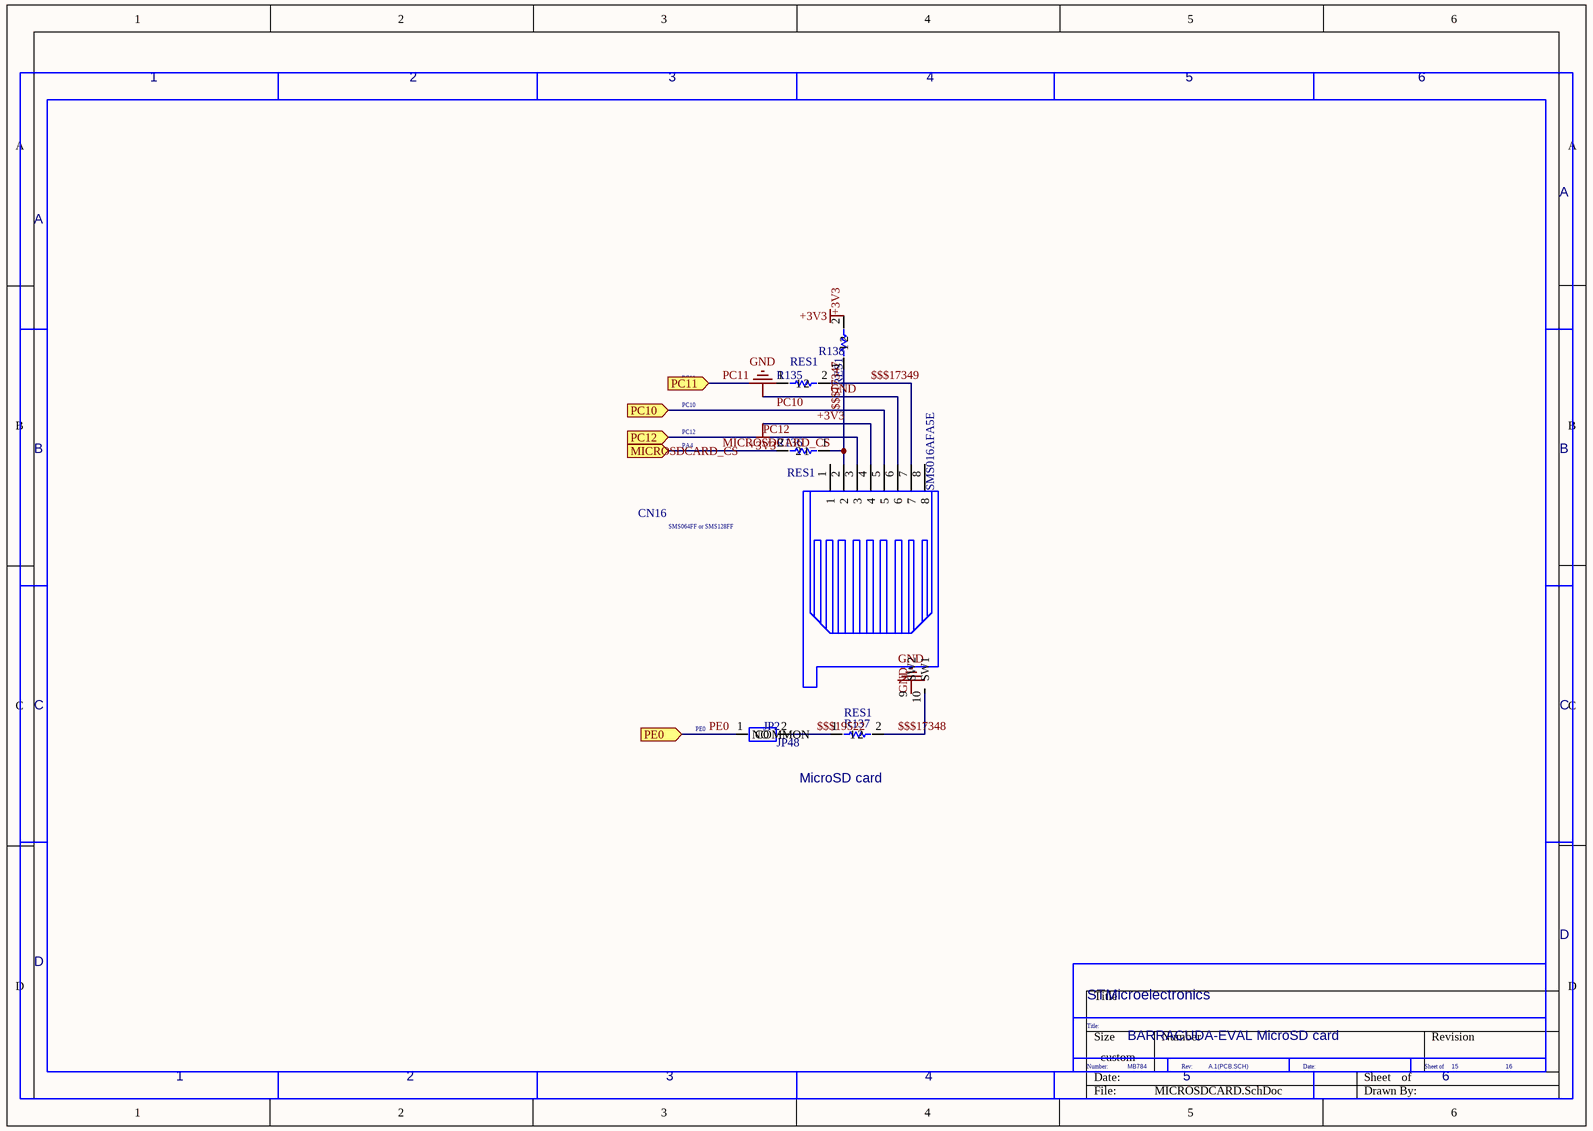
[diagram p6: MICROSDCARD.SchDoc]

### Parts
CN16  SMS016AFA5E
JP48  JP2
R135  RES1
R136  RES1
R137  RES1
R138  RES1

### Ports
MICROSDCARD_CS, PC10, PC11, PC12, PE0

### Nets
+3V3: CN16.4 R138.2
GND: CN16.6 CN16.9(SW2)  [project net $$$275]
$$$17347: CN16.2 CN16.5 R136.1 R138.1 ; port PC10  [also labelled PC10]
$$$17348: CN16.10(SW1) R137.2
$$$17349: CN16.7 R135.2
$$$19522: JP48.2(NO) R137.1
MICROSDCARD_CS: R136.2 ; port MICROSDCARD_CS
PC11: R135.1 ; port PC11
PC12: CN16.3 ; port PC12
PE0: JP48.1(COMMON) ; port PE0

Not connected (* = marked no-connect by the designer): CN16 1 8

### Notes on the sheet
- 1
- 2
- 3
- 4
- 5
- 6
- A
- PC10
- PC11
- B
- PA4
- PC12
- SMS064FF or SMS128FF
- C
- (near JP48) PE0
- MicroSD card
- D
- STMicroelectronics
- Number:
- Title:
- BARRACUDA-EVAL MicroSD card
- MB784
- Rev:
- A.1(PCB.SCH)
- Date:
- Sheet of
- 15
- 16

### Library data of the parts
CN16 = SMS016AFA5E: PCB DECAL: MSD(PJS008)
JP48 = JP2: PCB DECAL: SIP2
R135-R138 = RES1: as R87 on sheet EXTENSIONCONNECTOR

## Sheet MOTORCONTROL.SchDoc
size 297 x 210 mm
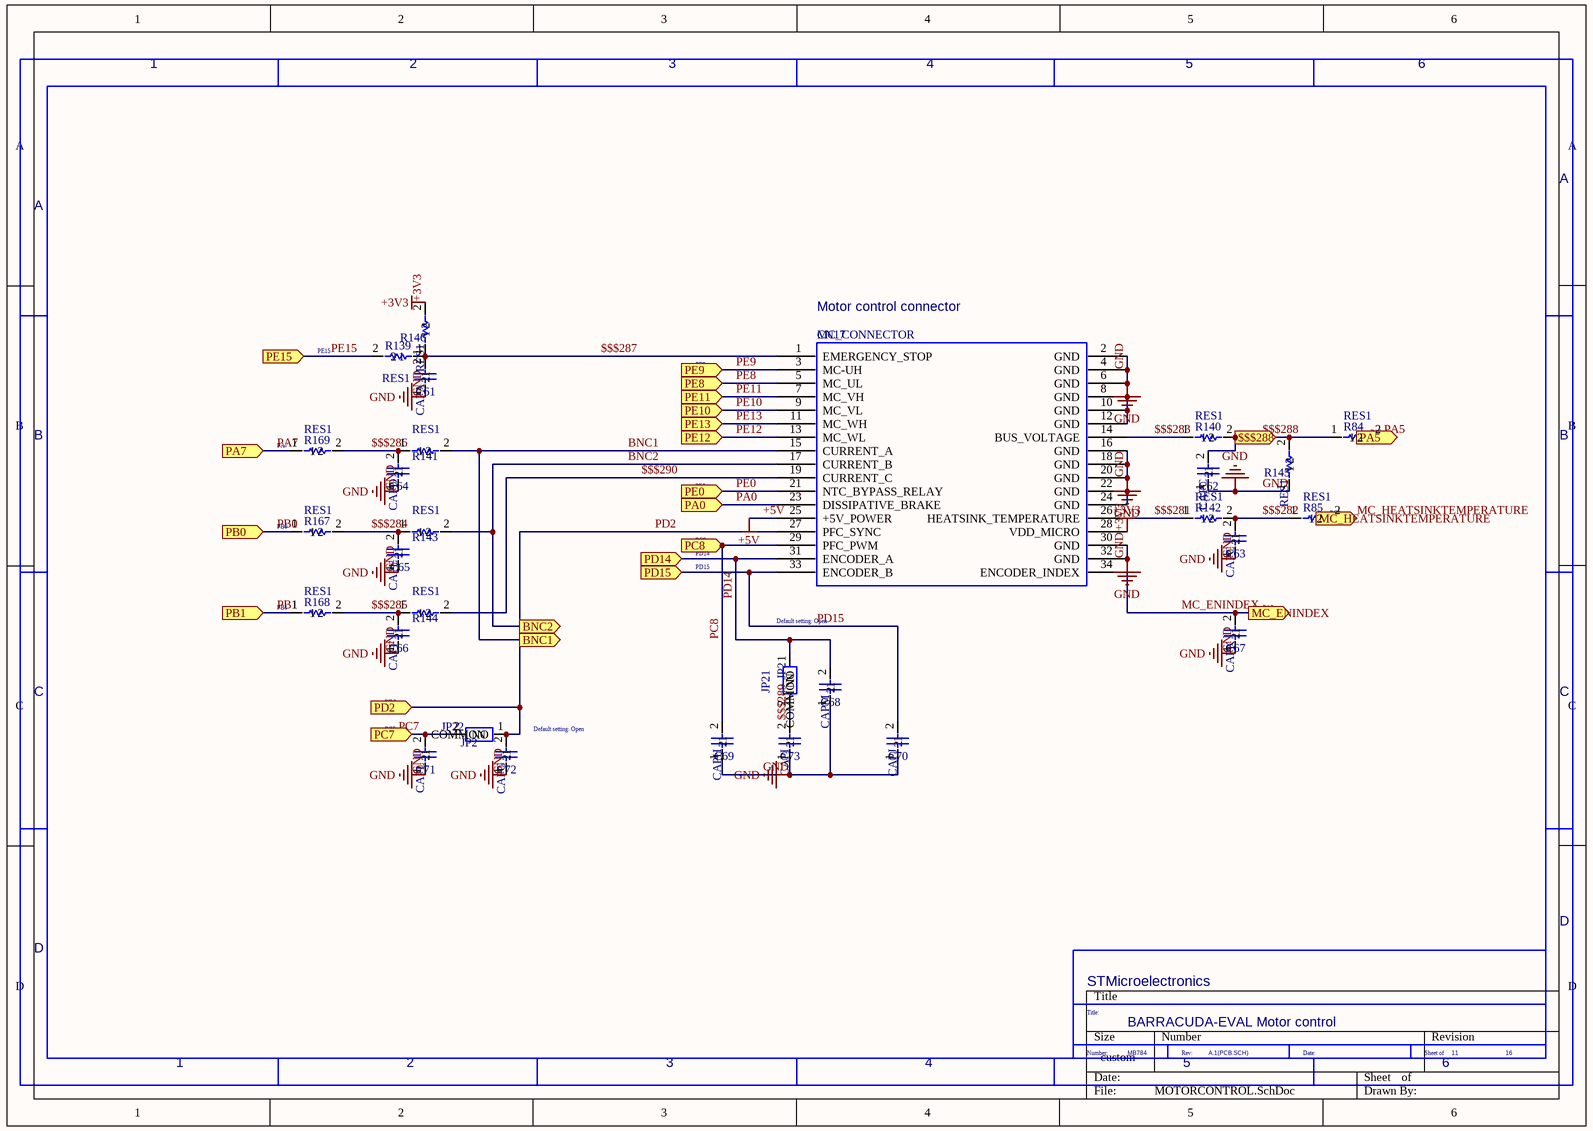
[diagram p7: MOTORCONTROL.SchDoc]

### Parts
C61  CAPA
C62  CAPC
C63  CAPC
C64  CAPD
C65  CAPE
C66  CAPF
C67  CAPK
C68  CAPM
C69  CAPH
C70  CAPJ
C71  CAPL
C72  CAPG
C73  CAPI
CN17  MC_CONNECTOR
JP21  JP2
JP22  JP2
R84  RES1
R85  RES1
R139  RES1
R140  RES1
R141  RES1
R142  RES1
R143  RES1
R144  RES1
R145  RES1
R146  RES1
R167  RES1
R168  RES1
R169  RES1

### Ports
$$$288, BNC1, BNC2, MC_ENINDEX, MC_HEATSINKTEMPERATURE, PA0, PA5, PA7, PB0, PB1, PC7, PC8, PD2, PD14, PD15, PE0, PE8, PE9, PE10, PE11, PE12, PE13, PE15

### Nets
+3V3: CN17.28(VDD_MICRO) R146.2
+5V: CN17.25(+5V_POWER)
GND: C61.1 C62.1 C63.1 C64.1 C65.1 C66.1 C67.1 C68.1 C69.1 C70.1 C71.1 C72.1 C73.1 CN17.2(GND) CN17.4(GND) CN17.6(GND) CN17.8(GND) CN17.10(GND) CN17.12(GND) CN17.16(GND) CN17.18(GND) CN17.20(GND) CN17.22(GND) CN17.24(GND) CN17.30(GND) CN17.32(GND) R145.1  [project net $$$275]
$$$281: CN17.26(HEATSINK_TEMPERATURE) R142.1
$$$282: C63.2 R85.1 R142.2
$$$283: CN17.14(BUS_VOLTAGE) R140.1
$$$284: C65.2 R143.1 R167.2
$$$285: C66.2 R144.1 R168.2
$$$286: C64.2 R141.1 R169.2
$$$287: C61.2 CN17.1(EMERGENCY_STOP) R139.1 R146.1
$$$288: C62.2 R84.1 R140.2 R145.2 ; port $$$288
$$$289: C73.2 JP21.2(NO)
$$$290: CN17.19(CURRENT_C) R144.2
BNC1: C72.2 CN17.15(CURRENT_A) CN17.17(CURRENT_B) CN17.27(PFC_SYNC) JP22.1(COMMON) R141.2 R143.2 ; port BNC2, port BNC1, port PD2  [also labelled BNC2, PD2]
MC_ENINDEX: C67.2 CN17.34(ENCODER_INDEX) ; port MC_ENINDEX
MC_HEATSINKTEMPERATURE: R85.2 ; port MC_HEATSINKTEMPERATURE
PA0: CN17.23(DISSIPATIVE_BRAKE) ; port PA0
PA5: R84.2 ; port PA5
PA7: R169.1 ; port PA7
PB0: R167.1 ; port PB0
PB1: R168.1 ; port PB1
PC7: C71.2 JP22.2(NO) ; port PC7
PC8: C69.2 CN17.29(PFC_PWM) ; port PC8
PD14: C68.2 CN17.31(ENCODER_A) JP21.1(COMMON) ; port PD14
PD15: C70.2 CN17.33(ENCODER_B) ; port PD15
PE0: CN17.21(NTC_BYPASS_RELAY) ; port PE0
PE8: CN17.5(MC_UL) ; port PE8
PE9: CN17.3(MC-UH) ; port PE9
PE10: CN17.9(MC_VL) ; port PE10
PE11: CN17.7(MC_VH) ; port PE11
PE12: CN17.13(MC_WL) ; port PE12
PE13: CN17.11(MC_WH) ; port PE13
PE15: R139.2 ; port PE15

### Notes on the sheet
- 1
- 2
- 3
- 4
- 5
- 6
- A
- (near CN17) Motor control connector
- PE15
- PE10
- PE11
- PE8
- PE9
- B
- (near R169) PA7
- PE12
- PE13
- (near R84) PA5
- (near R167) PB0
- PC8
- PA0
- PE0
- (near R85) PC0
- (near R168) PB1
- PD15
- PD14
- (near C67) PA3
- Default setting: Open
- C
- (near C71) PC7
- PD2
- D
- Title:
- STMicroelectronics
- Number:
- BARRACUDA-EVAL Motor control
- MB784
- Rev:
- A.1(PCB.SCH)
- Date:
- Sheet of
- 11
- 16

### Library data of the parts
C61 = CAPA: as C52 on sheet IOPERIPHERALS
C62 = CAPC: Capacitor; Value: 100pF; PCB DECAL: 0603C
C63 = CAPC: Capacitor; Value: 100pF; PCB DECAL: RAD-0.3
C64 = CAPD: Capacitor; Value: 100pF; PCB DECAL: RAD-0.3
C65 = CAPE: Capacitor; Value: 100pF; PCB DECAL: RAD-0.3
C66 = CAPF: Capacitor; Value: 100pF; PCB DECAL: RAD-0.3
C67 = CAPK: Capacitor; Value: 100pF; PCB DECAL: RAD-0.3
C68 = CAPM: Capacitor; Value: 100pF; PCB DECAL: RAD-0.3
C69 = CAPH: Capacitor; Value: 100pF; PCB DECAL: RAD-0.3
C70 = CAPJ: Capacitor; Value: 100pF; PCB DECAL: RAD-0.3
C71 = CAPL: Capacitor; Value: 100pF; PCB DECAL: RAD-0.3
C72 = CAPG: Capacitor; Value: 100pF; PCB DECAL: RAD-0.3
C73 = CAPI: Capacitor; Value: 100pF; PCB DECAL: RAD-0.3
CN17 = MC_CONNECTOR: PCB DECAL: IDC34S
JP21 JP22 = JP2: PCB DECAL: SIP2
R84 R85 R140-R145 R167-R169 = RES1: Resistor; Value: 1K; PCB DECAL: 0603
R139 R146 = RES1: as R87 on sheet EXTENSIONCONNECTOR

## Sheet POWER.SchDoc
size 297 x 210 mm
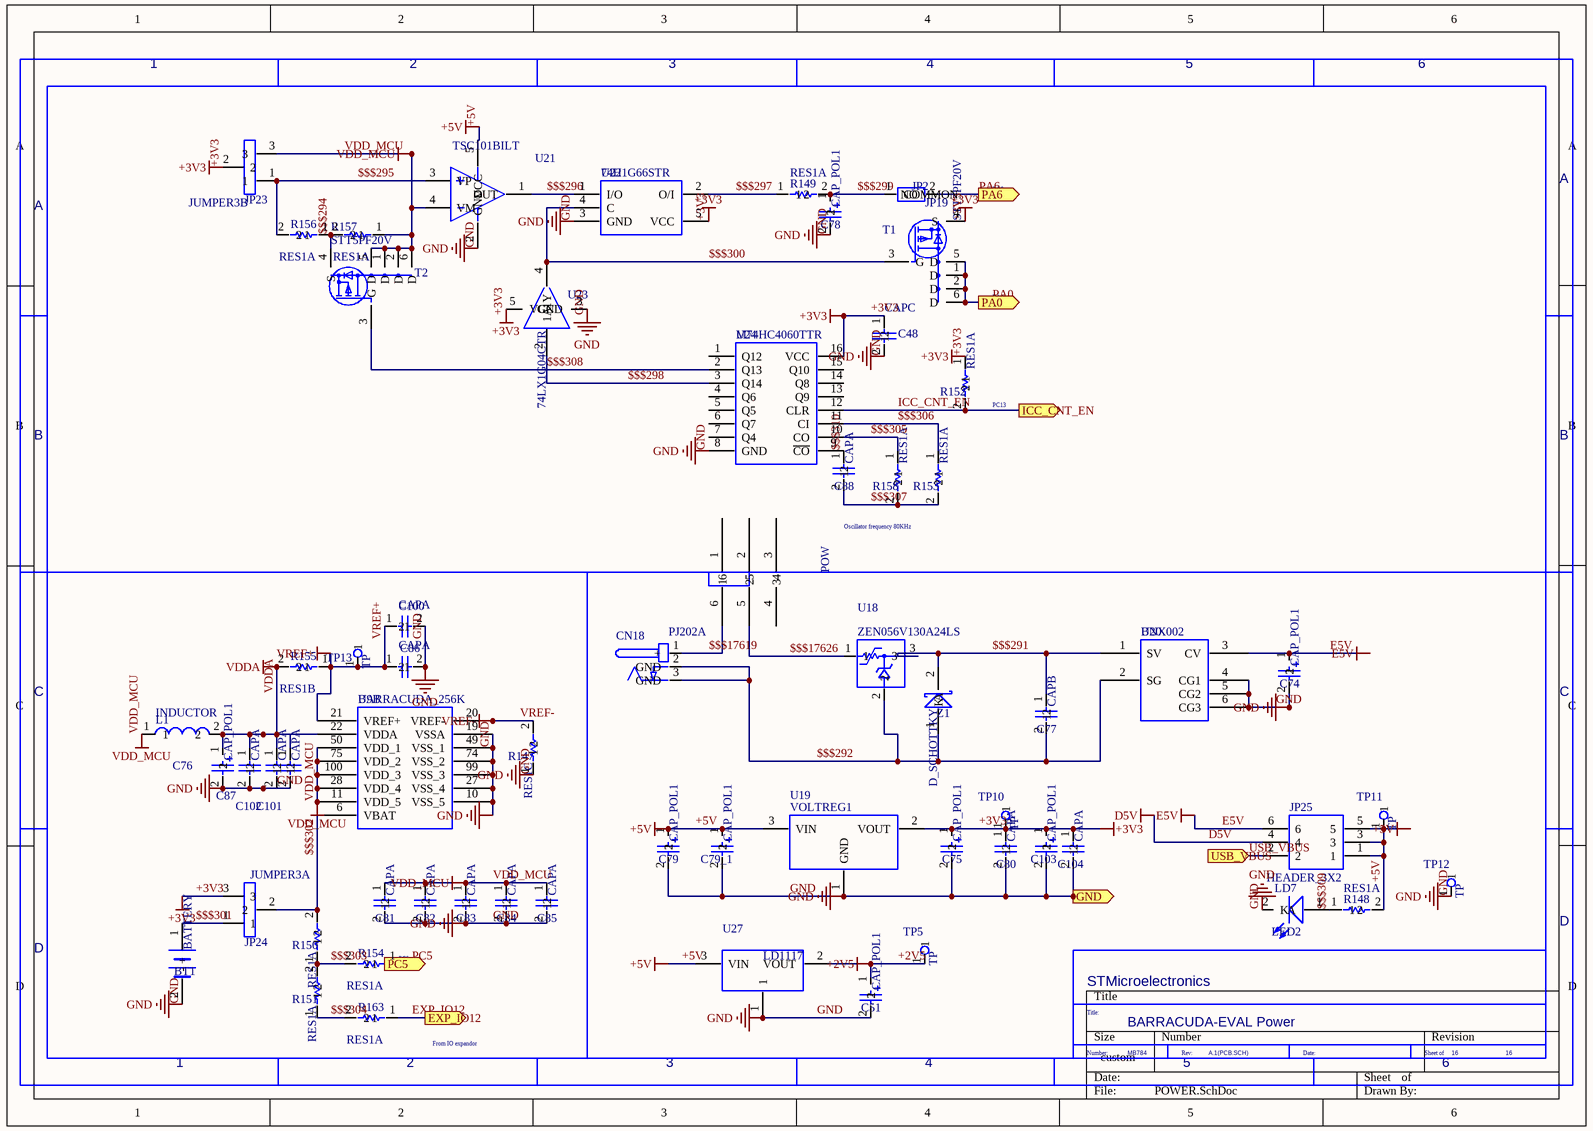
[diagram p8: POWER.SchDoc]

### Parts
BT1  BATTERY
C48  CAPC
C51  CAP_POL1
C74  CAP_POL1
C75  CAP_POL1
C76  CAP_POL1
C77  CAPB
C78  CAP_POL1
C79  CAP_POL1
C79_1  CAP_POL1
C80  CAPA
C81  CAPA
C82  CAPA
C83  CAPA
C84  CAPA
C85  CAPA
C86  CAPA
C87  CAPA
C88  CAPA
C100  CAPA
C101  CAPA
C102  CAPA
C103  CAP_POL1
C104  CAPA
CN18  PJ202A
JP19  JP2
JP23  JUMPER3B
JP24  JUMPER3A
JP25  HEADER_3X2
L1  INDUCTOR
LD7  LED2
POW  POW_MY  (value not drawn)
R147  RES1C
R148  RES1A
R149  RES1A
R150  RES1A
R151  RES1A
R152  RES1A
R153  RES1A
R154  RES1A
R155  RES1B
R156  RES1A
R157  RES1A
R158  RES1A
R163  RES1A
T1  STT5PF20V
T2  STT5PF20V
TP5  TP
TP10  TP
TP11  TP
TP12  TP
TP13  TP
U9  BARRACUDA_256K  (part B of 2)
U18  ZEN056V130A24LS
U19  VOLTREG1
U20  BNX002
U21  TSC101BILT
U22  74H1G66STR
U23  74LX1G04CTR
U24  M74HC4060TTR
U27  LD1117
Z1  D_SCHOTTKY

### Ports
EXP_IO12, GND, ICC_CNT_EN, PA0, PA6, PC5, USB_VBUS

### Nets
+2V5: C51.1 TP5.1 U27.2(VOUT)
+3V3: C48.1 C75.1 C80.1 C103.1 C104.1 JP23.2 JP24.3 R152.1 T1.4(S) TP10.1 U19.2(VOUT) U22.5(VCC) U23.5(VCC) U24.16(VCC)
+5V: C79.1 C79_1.1 JP25.1 JP25.3 JP25.5 R148.2 TP11.1 U19.3(VIN) U21.5(VCC) U27.3(VIN)
D5V: JP25.4
E5V: C74.1 JP25.6 U20.3(CV)
GND: BT1.2(-) C48.2 C51.2 C74.2 C75.2 C76.2 C78.2 C79.2 C79_1.2 C80.2 C81.2 C82.2 C83.2 C84.2 C85.2 C86.2 C87.2 C100.2 C101.2 C102.2 C103.2 C104.2 LD7.2(K) R147.1 TP12.1 U9.10(VSS_5) U9.19(VSSA) U9.27(VSS_4) U9.49(VSS_1) U9.74(VSS_2) U9.99(VSS_3) U19.1(GND) U20.4(CG1) U20.5(CG2) U20.6(CG3) U21.2(GND) U22.3(GND) U23.3(GND) U24.8(GND) U27.1 ; port GND  [project net $$$275]
NC: U23.1(NC)
VDD_MCU: C81.1 C82.1 C83.1 C84.1 C85.1 JP23.3 L1.1 R157.1 T2.1(D) T2.2(D) T2.5(D) T2.6(D) U9.11(VDD_5) U9.28(VDD_4) U9.50(VDD_1) U9.75(VDD_2) U9.100(VDD_3) U21.4(VM)
VDDA: C76.1 C87.1 C101.1 C102.1 L1.2 R155.2 U9.22(VDDA)
VREF+: C86.1 C100.1 R155.1 TP13.1 U9.21(VREF+)
VREF-: R147.2 U9.20(VREF-)
$$$291: C77.1 U18.3 U20.1(SV) Z1.2(K)
$$$292: C77.2 CN18.2(GND) CN18.3(GND) U18.2 U20.2(SG) Z1.1(A)
$$$294: R156.1 R157.2 T2.4(S)
$$$295: JP23.1 R156.2 U21.3(VP)
$$$296: U21.1(OUT) U22.1(I/O)
$$$297: R149.1 U22.2(O/I)
$$$298: T2.3(G) U23.2(1A) U24.2(Q13) U24.3(Q14)  [also labelled $$$308]
$$$299: C78.1 JP19.1(COMMON) R149.2
$$$300: T1.3(G) U22.4(C) U23.4(1Y)
$$$301: BT1.1(+) JP24.1
$$$302: JP24.2 R150.2 U9.6(VBAT)
$$$303: R150.1 R151.2 R154.2
$$$304: R151.1 R163.2
$$$305: R158.1 U24.10(CO)
$$$306: R153.1 U24.11(CI)
$$$307: C88.2 R153.2 R158.2
$$$309: LD7.1(A) R148.1
$$$310: C88.1 U24.9(~{CO})
$$$17619: CN18.1(+) POW.6
$$$17626: POW.5 U18.1
EXP_IO12: R163.1 ; port EXP_IO12  [project net EXP_IO11]
ICC_CNT_EN: R152.2 U24.12(CLR) ; port ICC_CNT_EN
PA0: T1.1(D) T1.2(D) T1.5(D) T1.6(D) ; port PA0
PA6: JP19.2(NO) ; port PA6
PC5: R154.1 ; port PC5
USB_VBUS: JP25.2 ; port USB_VBUS

Not connected (* = marked no-connect by the designer): POW 1 2 3 4; U24 1(Q12) 4(Q6) 5(Q5) 6(Q7) 7(Q4) 13(Q9) 14(Q8) 15(Q10)

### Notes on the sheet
- 1
- 2
- 3
- 4
- 5
- 6
- A
- PA6
- PA0
- (near R152) PC13
- B
- Oscillator frequency 80KHz
- C
- D
- (near R154) PC5
- Title:
- STMicroelectronics
- (near R163) 2
- (near R163) From IO expandor
- Number:
- BARRACUDA-EVAL Power
- MB784
- Rev:
- A.1(PCB.SCH)
- Date:
- Sheet of
- 16
- Labels drawn without touching a wire or pin: +3V3, GND

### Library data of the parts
BT1 = BATTERY: PCB DECAL: BATT
C48 = CAPC: PCB DECAL: 0603C
C51 C75 C76 C78 C103 = CAP_POL1: Polarized Capacitor (Radial); Value: 10uF; PCB DECAL: TAN-B
C74 = CAP_POL1: Polarized Capacitor (Radial); Value: 47uF; PCB DECAL: C160M
C77 = CAPB: Capacitor; Value: 100pF; PCB DECAL: 0603P
C79 C79_1 = CAP_POL1: Polarized Capacitor (Radial); Value: 10uF; PCB DECAL: C310M
C80 C104 = CAPA: Capacitor; Value: 10nF; PCB DECAL: 0603P
C81-C88 C100-C102 = CAPA: Capacitor; Value: 10nF; PCB DECAL: 0603
CN18 = PJ202A: PCB DECAL: DC10B
JP19 = JP2: PCB DECAL: SIP2
JP23 = JUMPER3B: PCB DECAL: SIP3
JP24 = JUMPER3A: PCB DECAL: SIP3
JP25 = HEADER_3X2: Header, 3-Pin, Dual row; PCB DECAL: 2*3P
L1 = INDUCTOR: Value: 100uH; PCB DECAL: 0603
LD7 = LED2: as LD1 on sheet IOPERIPHERALS
R147 = RES1C: as R114 on sheet IOPERIPHERALS
R148-R154 R156-R158 R163 = RES1A: as R86 on sheet IOPERIPHERALS
R155 = RES1B: as R117 on sheet IOPERIPHERALS
U9 = BARRACUDA_256K: PCB DECAL: TQFP100
U18 = ZEN056V130A24LS: PCB DECAL: polyzen
U19 = VOLTREG1: PCB DECAL: D2PAK/A
U20 = BNX002: PCB DECAL: BNX001
U24 = M74HC4060TTR: PCB DECAL: TSSOP16
U27 = LD1117: PCB DECAL: SOT-223
Z1 = D_SCHOTTKY: Schottky Diode; Code - JEDEC: DO-214-AA; PCB DECAL: 1R1C

## Sheet SMARTCARD.SchDoc
size 297 x 210 mm
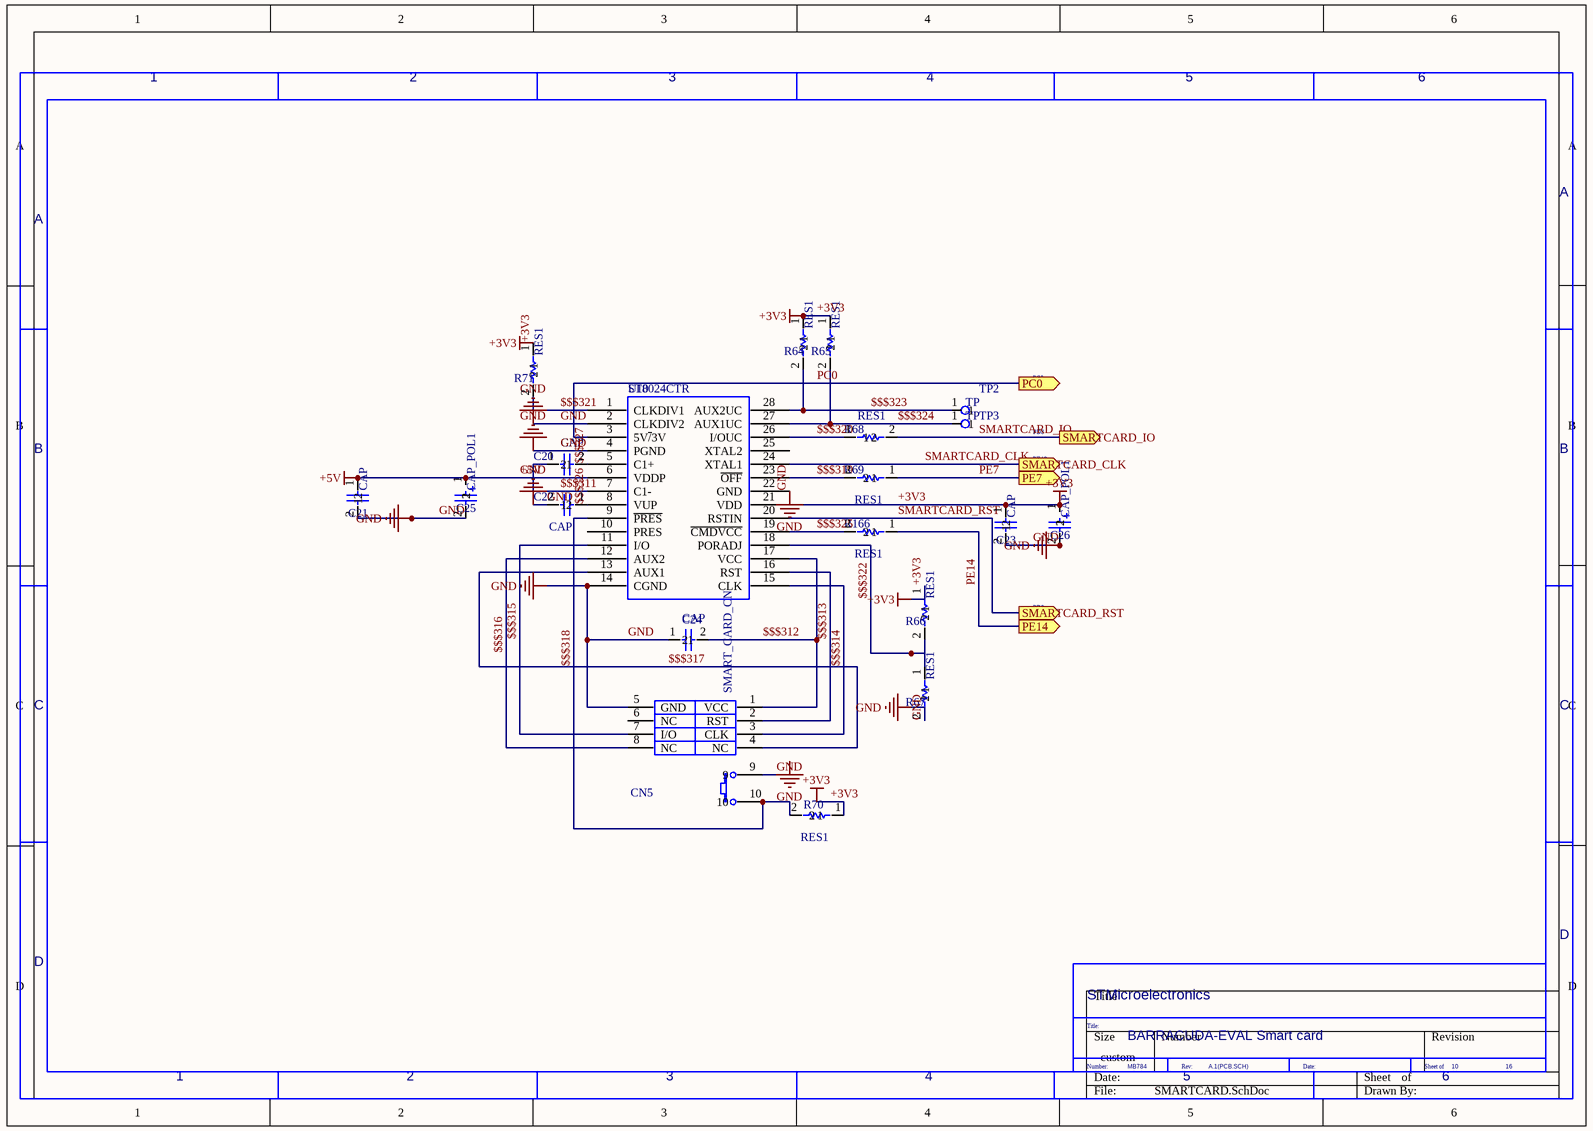
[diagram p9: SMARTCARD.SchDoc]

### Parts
C20  CAP
C21  CAP
C22  CAP
C23  CAP
C24  CAP
C25  CAP_POL1
C26  CAP_POL1
CN5  SMART_CARD_CN
R64  RES1
R65  RES1
R66  RES1
R67  RES1
R68  RES1
R69  RES1
R70  RES1
R71  RES1
R166  RES1
TP2  TP
TP3  TP
U10  ST8024CTR

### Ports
PC0, PE7, PE14, SMARTCARD_CLK, SMARTCARD_IO, SMARTCARD_RST

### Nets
+3V3: C23.1 C26.1 R64.1 R65.1 R66.1 R70.1 R71.1 U10.21(VDD)
+5V: C21.1 C25.1 U10.6(VDDP)
GND: C21.2 C22.2 C23.2 C24.1 C25.2 C26.2 CN5.5(GND) CN5.9 R67.2 U10.2(CLKDIV2) U10.4(PGND) U10.14(CGND) U10.22(GND)  [project net $$$275]
$$$311: C20.1 U10.7(C1-)
$$$312: C24.2 CN5.1(VCC) U10.17(VCC)
$$$313: CN5.2(RST) U10.16(RST)
$$$314: CN5.3(CLK) CN5.4(NC) CN5.10 R70.2 U10.9(~{PRES}) U10.13(AUX1) U10.15(CLK)  [also labelled $$$317, $$$318]
$$$315: CN5.7(I/O) U10.11(I/O)
$$$316: CN5.8(NC) U10.12(AUX2)
$$$319: R69.2 U10.23(~{OFF})
$$$320: R68.1 U10.26(I/OUC)
$$$321: R71.2 U10.1(CLKDIV1)
$$$322: R66.2 R67.1 U10.18(PORADJ)
$$$323: R64.2 TP2.1 U10.28(AUX2UC)
$$$324: R65.2 TP3.1 U10.27(AUX1UC)
$$$325: R166.2 U10.19(~{CMDVCC})
$$$326: C22.1 U10.8(VUP)
$$$327: C20.2 U10.5(C1+)
PC0: U10.3(5V~{/}3V) ; port PC0
PE7: R69.1 ; port PE7
PE14: R166.1 ; port PE14
SMARTCARD_CLK: U10.24(XTAL1) ; port SMARTCARD_CLK
SMARTCARD_IO: R68.2 ; port SMARTCARD_IO
SMARTCARD_RST: U10.20(RSTIN) ; port SMARTCARD_RST

Not connected (* = marked no-connect by the designer): CN5 6(NC); U10 10(PRES) 25(XTAL2)

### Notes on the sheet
- 1
- 2
- 3
- 4
- 5
- 6
- A
- PC0
- B
- PE7
- PD10
- PD8
- PD9
- PE14
- C
- D
- STMicroelectronics
- Number:
- Title:
- BARRACUDA-EVAL Smart card
- MB784
- Rev:
- A.1(PCB.SCH)
- Date:
- Sheet of
- 10
- 16

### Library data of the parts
C20-C24 = CAP: Capacitor; Value: 100nF; PCB DECAL: 0603P
C25 C26 = CAP_POL1: Polarized Capacitor (Radial); Value: 100pF; PCB DECAL: TAN-B
CN5 = SMART_CARD_CN: PCB DECAL: SAM(C816)
R64-R71 R166 = RES1: as R87 on sheet EXTENSIONCONNECTOR
U10 = ST8024CTR: PCB DECAL: SO28

## Sheet USART&IRDA.SchDoc
size 297 x 210 mm
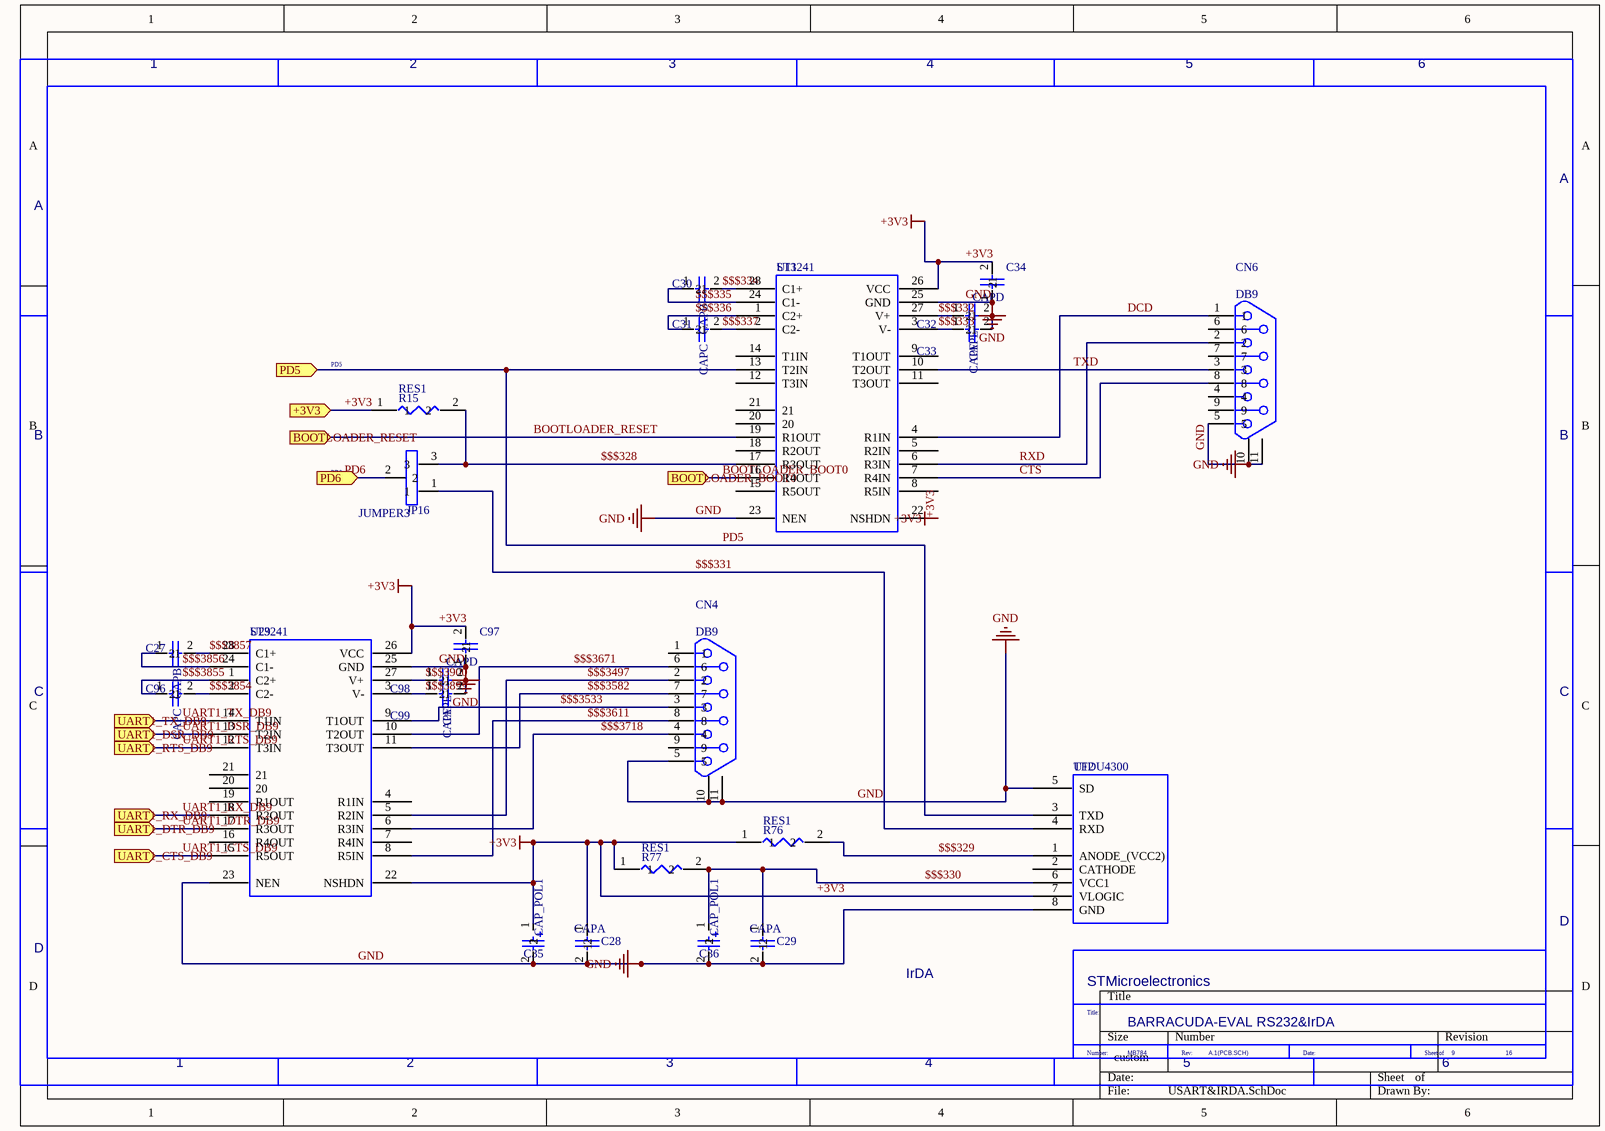
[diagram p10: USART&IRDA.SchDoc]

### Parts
C27  CAPB
C28  CAPA
C29  CAPA
C30  CAPB
C31  CAPC
C32  CAPE
C33  CAPF
C34  CAPD
C35  CAP_POL1
C36  CAP_POL1
C96  CAPC
C97  CAPD
C98  CAPE
C99  CAPF
CN4  DB9
CN6  DB9
JP16  JUMPER3
R15  RES1
R76  RES1
R77  RES1
U11  ST3241
U12  TFDU4300
U29  ST3241

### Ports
+3V3, BOOTLOADER_BOOT0, BOOTLOADER_RESET, PD5, PD6, UART1_CTS_DB9, UART1_DSR_DB9, UART1_DTR_DB9, UART1_RTS_DB9, UART1_RX_DB9, UART1_TX_DB9

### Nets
+3V3: C28.1 C34.2 C35.1 C97.2 R15.1 R76.1 R77.1 U11.22(NSHDN) U11.26(VCC) U12.7(VLOGIC) U29.22(NSHDN) U29.26(VCC) ; port +3V3
GND: C28.2 C29.2 C32.2 C33.2 C34.1 C35.2 C36.2 C97.1 C98.2 C99.2 CN4.5 CN4.10 CN4.11 CN6.5 CN6.10 CN6.11 U11.23(NEN) U11.25(GND) U12.5(SD) U12.8(GND) U29.23(NEN) U29.25(GND)  [project net $$$275]
$$$328: JP16.3 R15.2 U11.17(R3OUT)
$$$329: R76.2 U12.1(ANODE_(VCC2))
$$$330: C29.1 C36.1 R77.2 U12.6(VCC1)
$$$331: JP16.1 U12.4(RXD)
$$$332: C32.1 U11.27(V+)
$$$333: C33.1 U11.3(V-)
$$$334: C30.2 U11.28(C1+)
$$$335: C30.1 U11.24(C1-)
$$$336: C31.1 U11.1(C2+)
$$$337: C31.2 U11.2(C2-)
$$$3497: CN4.2 U29.5(R2IN)
$$$3533: CN4.3 U29.9(T1OUT)
$$$3582: CN4.7 U29.11(T3OUT)
$$$3611: CN4.8 U29.8(R5IN)
$$$3671: CN4.6 U29.10(T2OUT)
$$$3718: CN4.4 U29.6(R3IN)
$$$3854: C96.2 U29.2(C2-)
$$$3855: C96.1 U29.1(C2+)
$$$3856: C27.1 U29.24(C1-)
$$$3857: C27.2 U29.28(C1+)
$$$3899: C99.1 U29.3(V-)
$$$3900: C98.1 U29.27(V+)
BOOTLOADER_BOOT0: U11.16(R4OUT) ; port BOOTLOADER_BOOT0
BOOTLOADER_RESET: U11.19(R1OUT) ; port BOOTLOADER_RESET
CTS: CN6.8 U11.7(R4IN)
DCD: CN6.1 U11.4(R1IN)
PD5: U11.13(T2IN) U12.3(TXD) ; port PD5
PD6: JP16.2 ; port PD6
RXD: CN6.2 U11.6(R3IN)
TXD: CN6.3 U11.10(T2OUT)
UART1_CTS_DB9: U29.15(R5OUT) ; port UART1_CTS_DB9
UART1_DSR_DB9: U29.13(T2IN) ; port UART1_DSR_DB9
UART1_DTR_DB9: U29.17(R3OUT) ; port UART1_DTR_DB9
UART1_RTS_DB9: U29.12(T3IN) ; port UART1_RTS_DB9
UART1_RX_DB9: U29.18(R2OUT) ; port UART1_RX_DB9
UART1_TX_DB9: U29.14(T1IN) ; port UART1_TX_DB9

Not connected (* = marked no-connect by the designer): CN4 1 9; CN6 4 6 7 9; U11 5(R2IN) 8(R5IN) 9(T1OUT) 11(T3OUT) 12(T3IN) 14(T1IN) 15(R5OUT) 18(R2OUT) 20 21; U12 2(CATHODE); U29 4(R1IN) 7(R4IN) 16(R4OUT) 19(R1OUT) 20 21

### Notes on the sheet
- 1
- 2
- 3
- 4
- 5
- 6
- A
- PD5
- B
- PD6
- C
- D
- IrDA
- Title:
- STMicroelectronics
- Number:
- BARRACUDA-EVAL RS232&IrDA
- MB784
- Rev:
- A.1(PCB.SCH)
- Date:
- Sheet of
- 9
- 16

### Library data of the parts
C27 C30 = CAPB: Capacitor; PCB DECAL: 0603
C28 = CAPA: Capacitor; UNNAMED1: Cap-Chip-Ceramic; UNNAMED2: Close to U9.Pin1; PCB DECAL: 0603P
C29 = CAPA: Capacitor; UNNAMED1: Cap-Chip-Ceramic; UNNAMED2: Close to U9.Pin6; UNNAMED4: Close to U9.Pin1; PCB DECAL: 0603P
C31 C96 = CAPC: Capacitor; PCB DECAL: 0603
C32 C98 = CAPE: Capacitor; PCB DECAL: 0603
C33 C99 = CAPF: Capacitor; PCB DECAL: 0603
C34 C97 = CAPD: Capacitor; PCB DECAL: 0603
C35 C36 = CAP_POL1: as C25 on sheet SMARTCARD
CN4 CN6 = DB9: PCB DECAL: DB9FLE
JP16 = JUMPER3: PCB DECAL: SIP3
R15 R76 R77 = RES1: PCB DECAL: 0603
U11 U29 = ST3241: PCB DECAL: SSOP28
U12 = TFDU4300: PCB DECAL: IR_VISHAY3

## Sheet USB_OTG_FS.SchDoc
size 297 x 210 mm
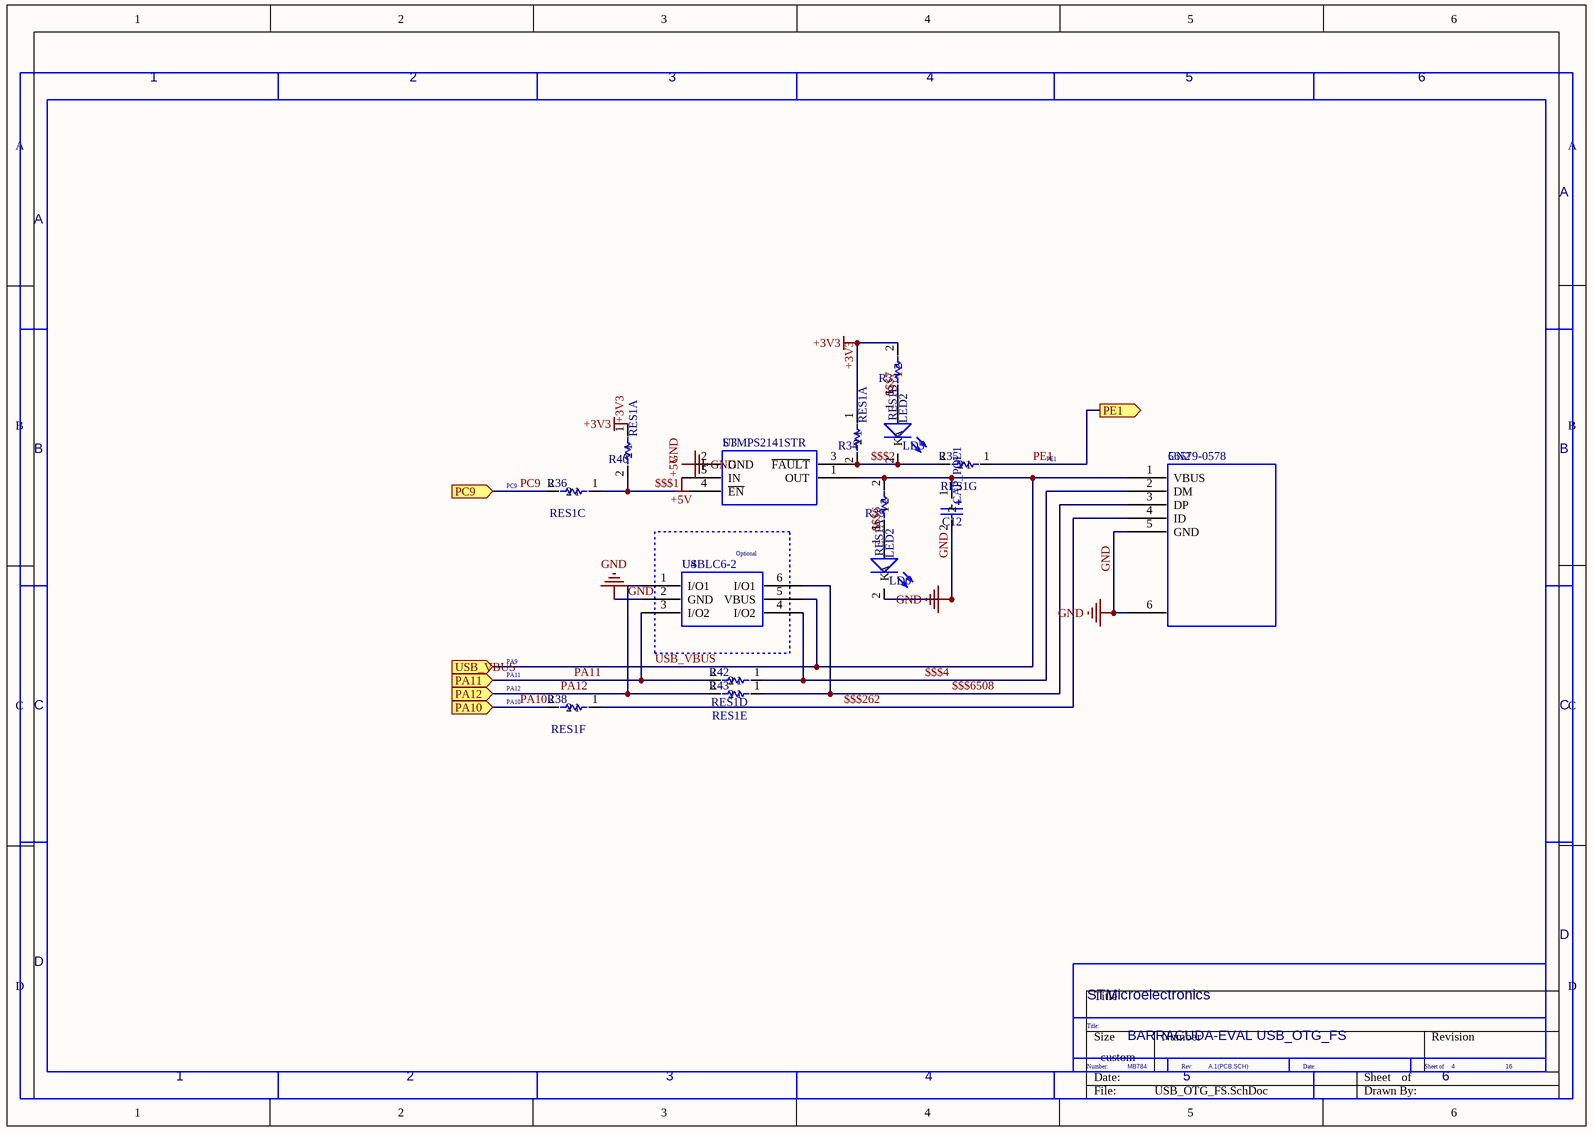
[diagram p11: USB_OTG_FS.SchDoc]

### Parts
C12  CAP_POL1
CN2  56579-0578
LD5  LED2
LD6  LED2
R33  RES1B
R34  RES1A
R35  RES1G
R36  RES1C
R38  RES1F
R39  RES1A
R40  RES1A
R42  RES1D
R43  RES1E
U3  STMPS2141STR
U4  USBLC6-2

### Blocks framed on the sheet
Optional: U4

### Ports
PA10, PA11, PA12, PC9, PE1, USB_VBUS

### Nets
+3V3: R33.2 R34.1 R40.1
+5V: U3.5(IN)
GND: C12.2 CN2.5(GND) CN2.6 LD6.2(K) R43.2 U3.2(GND) U4.1(I/O1) U4.2(GND) ; port PA12  [also labelled PA12]  [project net $$$275]
$$$1: R36.1 R40.2 U3.4(~{EN})
$$$2: LD5.2(K) R34.2 R35.2 U3.3(~{FAULT})
$$$4: CN2.2(DM) R42.1 U4.4(I/O2)
$$$6: LD6.1(A) R39.1
$$$7: LD5.1(A) R33.1
$$$262: CN2.4(ID) R38.1
$$$6508: CN2.3(DP) R43.1 U4.6(I/O1)
PA10: R38.2 ; port PA10
PA11: R42.2 U4.3(I/O2) ; port PA11
PC9: R36.2 ; port PC9
PE1: R35.1 ; port PE1
USB_VBUS: C12.1 CN2.1(VBUS) R39.2 U3.1(OUT) U4.5(VBUS) ; port USB_VBUS

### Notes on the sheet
- 1
- 2
- 3
- 4
- 5
- 6
- A
- B
- PE1
- (near R36) PC9
- (near R38) PA11
- PA9
- C
- (near R38) PA10
- (near R38) PA12
- D
- STMicroelectronics
- Number:
- Title:
- BARRACUDA-EVAL USB_OTG_FS
- MB784
- Rev:
- A.1(PCB.SCH)
- Date:
- Sheet of
- 16

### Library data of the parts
C12 = CAP_POL1: as C74 on sheet POWER
CN2 = 56579-0578: PCB DECAL: MINIAB
LD5 LD6 = LED2: as LD1 on sheet IOPERIPHERALS
R33 = RES1B: as R117 on sheet IOPERIPHERALS
R34 R39 R40 = RES1A: as R86 on sheet IOPERIPHERALS
R35 = RES1G: Resistor; Value: 1K; PCB DECAL: AXIAL-0.3
R36 = RES1C: as R114 on sheet IOPERIPHERALS
R38 = RES1F: as R106 on sheet IOPERIPHERALS
R42 = RES1D: as R115 on sheet IOPERIPHERALS
R43 = RES1E: as R107 on sheet IOPERIPHERALS
U3 = STMPS2141STR: PCB DECAL: SOT23-5L
U4 = USBLC6-2: PCB DECAL: SOT-666

## Sheet AUDIO.SchDoc
size 297 x 210 mm
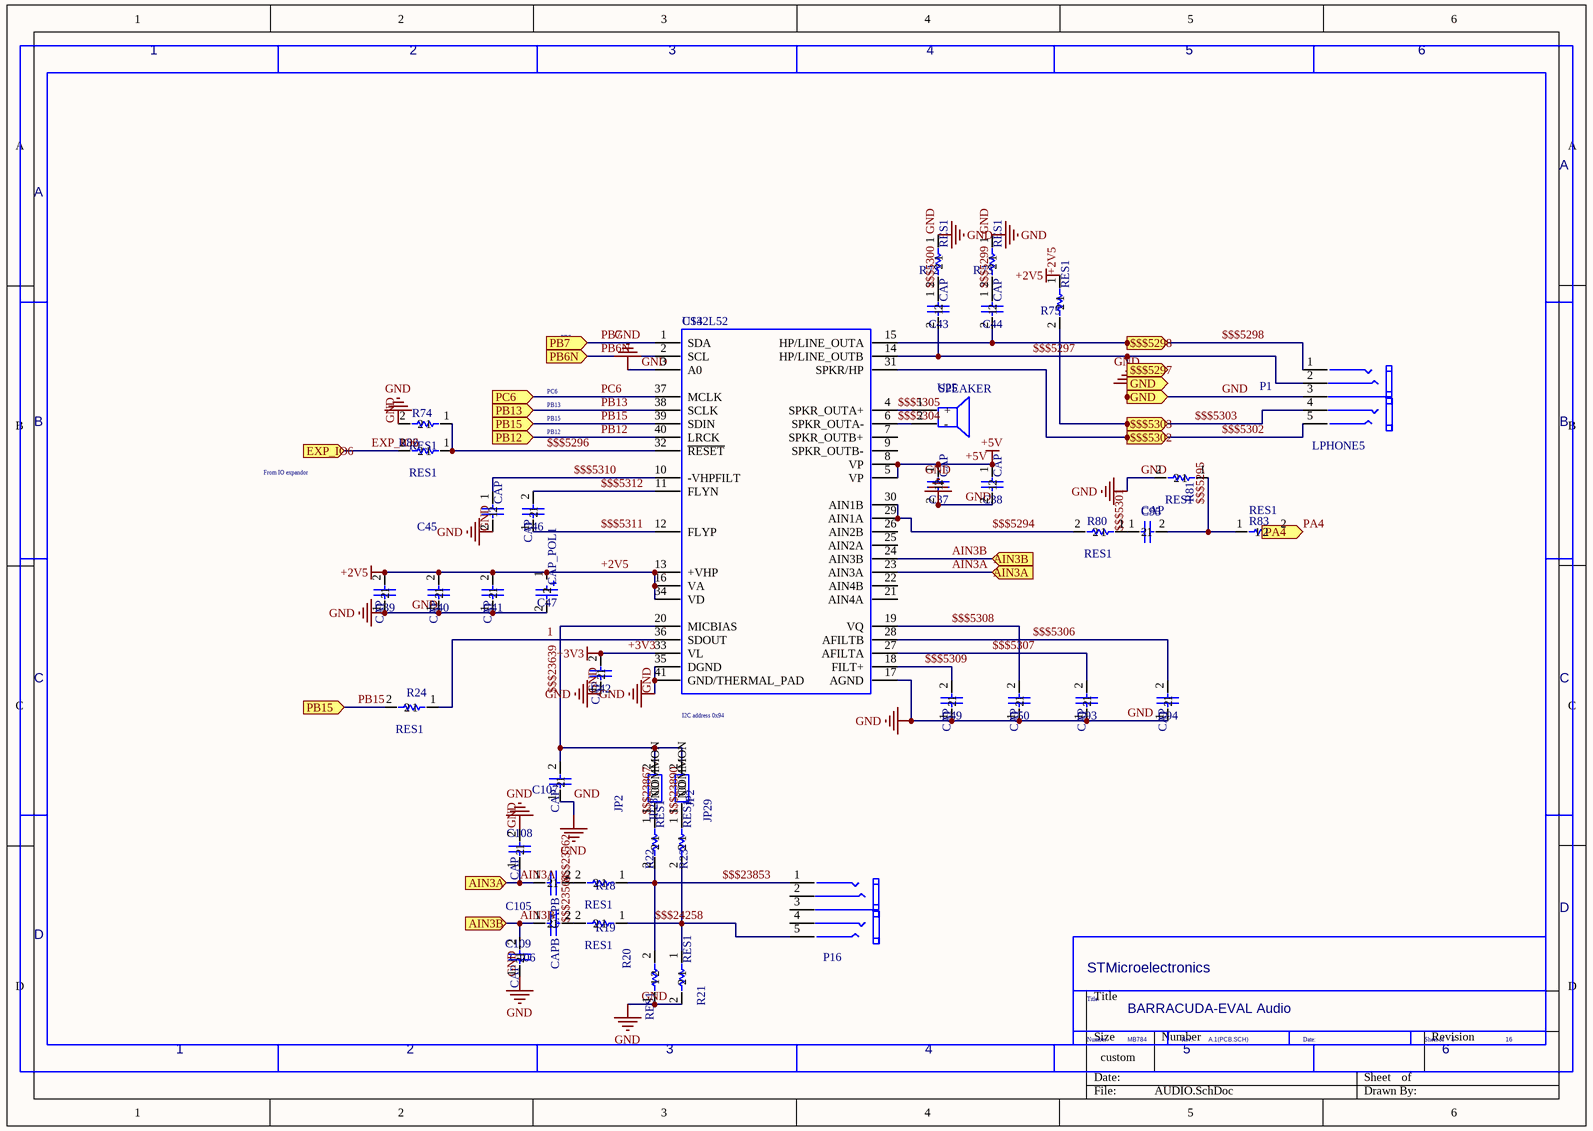
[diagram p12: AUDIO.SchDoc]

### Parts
C37  CAP
C38  CAP
C39  CAP
C40  CAP
C41  CAP
C42  CAP
C43  CAP
C44  CAP
C45  CAP
C46  CAP
C47  CAP_POL1
C49  CAP
C50  CAP
C93  CAP
C94  CAP
C95  CAP
C105  CAPB
C106  CAPB
C107  CAP
C108  CAP
C109  CAP
JP28  JP2
JP29  JP2
P1  LPHONE5
P16  LPHONE5  (value not drawn)
R18  RES1
R19  RES1
R20  RES1
R21  RES1
R22  RES1
R23  RES1
R24  RES1
R72  RES1
R73  RES1
R74  RES1
R75  RES1
R80  RES1
R81  RES1
R82  RES1
R83  RES1
U13  CS42L52
U25  SPEAKER

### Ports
$$$5297, $$$5298, $$$5302, $$$5303, AIN3A, AIN3B, EXP_IO6, GND, PA4, PB6N, PB7, PB12, PB13, PB15, PC6

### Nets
+2V5: C39.2 C40.2 C41.2 C47.1 R75.1 U13.13(+VHP) U13.16(VA) U13.34(VD)
+3V3: C42.2 U13.33(VL)
+5V: C37.1 C38.1 U13.5(VP) U13.8(VP)
GND: C37.2 C38.2 C39.1 C40.1 C41.1 C42.1 C45.2 C47.2 C49.1 C50.1 C93.1 C94.1 C107.1 C108.2 C109.1 P1.3 R20.1 R21.2 R72.1 R73.1 R74.2 R81.2 U13.3(A0) U13.17(AGND) U13.35(DGND) U13.41(GND/THERMAL_PAD) ; port GND  [project net $$$275]
1: R24.1 U13.36(SDOUT)
$$$5294: R80.2 U13.29(AIN1A) U13.30(AIN1B)
$$$5295: C95.2 R81.1 R83.1
$$$5296: R74.1 R82.1 U13.32(~{RESET})
$$$5297: C43.2 P1.2 U13.14(HP/LINE_OUTB) ; port $$$5297
$$$5298: C44.2 P1.1 U13.15(HP/LINE_OUTA) ; port $$$5298
$$$5299: C44.1 R73.2
$$$5300: C43.1 R72.2
$$$5301: C95.1 R80.1
$$$5302: P1.5 U13.31(SPKR/HP) ; port $$$5302
$$$5303: P1.4 R75.2 ; port $$$5303
$$$5304: U13.6(SPKR_OUTA-) U25.2(-)
$$$5305: U13.4(SPKR_OUTA+) U25.1(+)
$$$5306: C94.2 U13.28(AFILTB)
$$$5307: C93.2 U13.27(AFILTA)
$$$5308: C50.2 U13.19(VQ)
$$$5309: C49.2 U13.18(FILT+)
$$$5310: C45.1 U13.10(-VHPFILT)
$$$5311: C46.1 U13.12(FLYP)
$$$5312: C46.2 U13.11(FLYN)
$$$23562: C105.2 R18.2
$$$23564: C106.2 R19.2
$$$23639: C107.2 JP28.2(NO) JP29.2(NO) U13.20(MICBIAS)
$$$23853: P16.1 P16.5 R18.1 R19.1 R20.2 R21.1 R22.2 R23.2  [also labelled $$$24258]
$$$23867: JP28.1(COMMON) R22.1
$$$23890: JP29.1(COMMON) R23.1
AIN3A: C105.1 C108.1 U13.23(AIN3A) ; port AIN3A
AIN3B: C106.1 C109.2 U13.24(AIN3B) ; port AIN3B
EXP_IO6: R82.2 ; port EXP_IO6
PA4: R83.2 ; port PA4
PB6N: U13.2(SCL) ; port PB6N
PB7: U13.1(SDA) ; port PB7
PB12: U13.40(LRCK) ; port PB12
PB13: U13.38(SCLK) ; port PB13
PB15: R24.2 U13.39(SDIN) ; port PB15
PC6: U13.37(MCLK) ; port PC6

Not connected (* = marked no-connect by the designer): P16 2 3 4; U13 7(SPKR_OUTB+) 9(SPKR_OUTB-) 21(AIN4A) 22(AIN4B) 25(AIN2A) 26(AIN2B)

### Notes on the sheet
- 1
- 2
- 3
- 4
- 5
- 6
- A
- PB7
- PB13
- PC6
- PB6
- B
- From IO expandor
- PB12
- PB15
- C
- I2C address 0x94
- D
- Title:
- STMicroelectronics
- BARRACUDA-EVAL Audio
- Number:
- MB784
- Rev:
- A.1(PCB.SCH)
- Date:
- Sheet of
- 16

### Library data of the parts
C37-C46 C49 C50 C93-C95 C107-C109 = CAP: as C20 on sheet SMARTCARD
C47 = CAP_POL1: as C74 on sheet POWER
C105 C106 = CAPB: Capacitor; PCB DECAL: 0603
JP28 JP29 = JP2: PCB DECAL: SIP2
P1 P16 = LPHONE5: PCB DECAL: LPHONE5PAN
R18-R24 R72-R75 R80-R83 = RES1: as R87 on sheet EXTENSIONCONNECTOR
U13 = CS42L52: PCB DECAL: QFN40
U25 = SPEAKER: Loudspeaker; PCB DECAL: KS1508

## Sheet CAN.SchDoc
size 297 x 210 mm
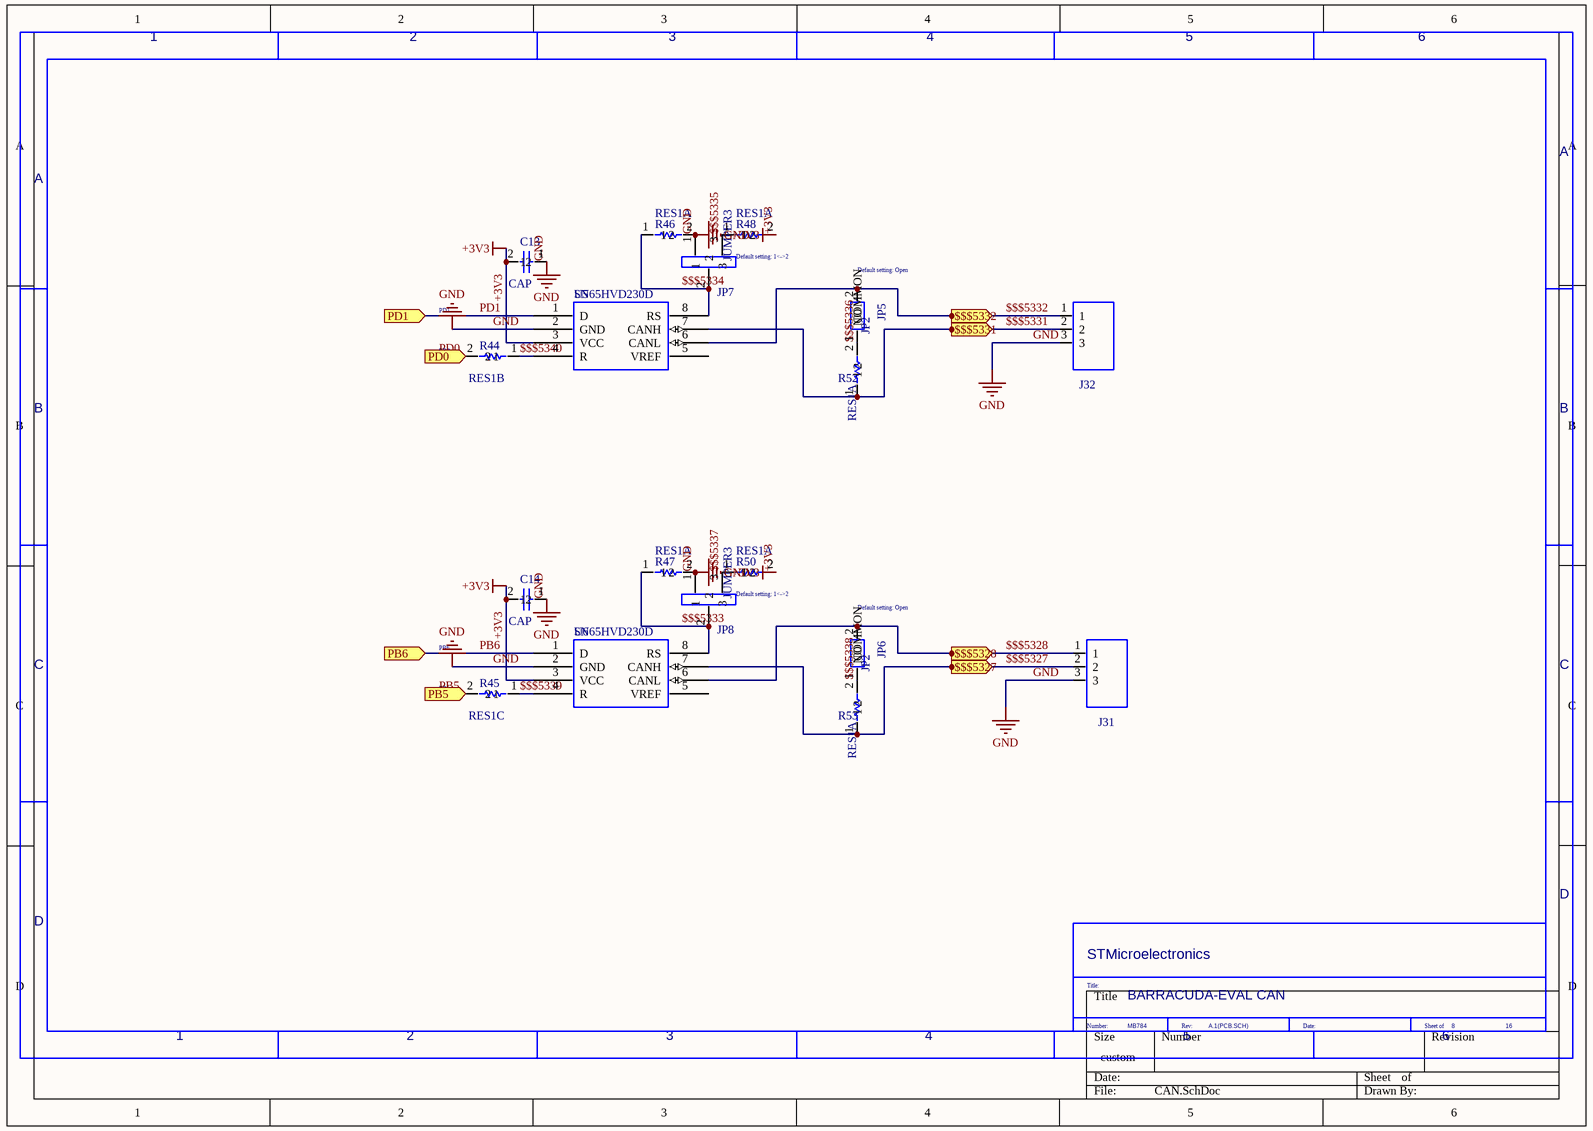
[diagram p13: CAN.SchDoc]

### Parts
C13  CAP
C14  CAP
J31  SIP3  (value not drawn)
J32  SIP3-CAN  (value not drawn)
JP5  JP2
JP6  JP2
JP7  JUMPER3
JP8  JUMPER3
R44  RES1B
R45  RES1C
R46  RES1A
R47  RES1A
R48  RES1A
R50  RES1A
R52  RES1A
R53  RES1A
U5  SN65HVD230D
U6  SN65HVD230D

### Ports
$$$5327, $$$5328, $$$5331, $$$5332, PB5, PB6, PD0, PD1

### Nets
+3V3: C13.2 C14.2 R48.2 R50.2 U5.3(VCC) U6.3(VCC)
GND: C13.1 C14.1 J31.3 J32.3 JP7.1 JP8.1 R46.2 R47.2 U5.2(GND) U6.2(GND)  [project net $$$275]
$$$5327: J31.2 R53.1 U6.7(CANH) ; port $$$5327
$$$5328: J31.1 JP6.2(NO) U6.6(CANL) ; port $$$5328
$$$5331: J32.2 R52.1 U5.7(CANH) ; port $$$5331
$$$5332: J32.1 JP5.2(NO) U5.6(CANL) ; port $$$5332
$$$5333: JP8.2 R47.1 U6.8(RS)
$$$5334: JP7.2 R46.1 U5.8(RS)
$$$5335: JP7.3 R48.1
$$$5336: JP5.1(COMMON) R52.2
$$$5337: JP8.3 R50.1
$$$5338: JP6.1(COMMON) R53.2
$$$5339: R45.1 U6.4(R)
$$$5340: R44.1 U5.4(R)
PB5: R45.2 ; port PB5  [project net PB11]
PB6: U6.1(D) ; port PB6
PD0: R44.2 ; port PD0
PD1: U5.1(D) ; port PD1

Not connected (* = marked no-connect by the designer): U5 5(VREF); U6 5(VREF)

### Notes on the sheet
- 1
- 2
- 3
- 4
- 5
- 6
- A
- Default setting: 1<->2
- (near JP5) Default setting: Open
- (near R44) PD1
- (near R44) PD0
- B
- (near JP6) Default setting: Open
- C
- (near R45) PB6
- (near R45) PB5
- D
- Title:
- STMicroelectronics
- BARRACUDA-EVAL CAN
- Number:
- MB784
- Rev:
- A.1(PCB.SCH)
- Date:
- Sheet of
- 8
- 16

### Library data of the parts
C13 C14 = CAP: as C20 on sheet SMARTCARD
J31 = SIP3: PCB DECAL: SIP3-CAN
JP5 JP6 = JP2: PCB DECAL: SIP2
JP7 JP8 = JUMPER3: PCB DECAL: SIP3
R44 = RES1B: as R117 on sheet IOPERIPHERALS
R45 = RES1C: as R114 on sheet IOPERIPHERALS
R46-R48 R50 R52 R53 = RES1A: as R86 on sheet IOPERIPHERALS
U5 U6 = SN65HVD230D: PCB DECAL: SO8

## Sheet ETHERNET.SchDoc
size 297 x 210 mm
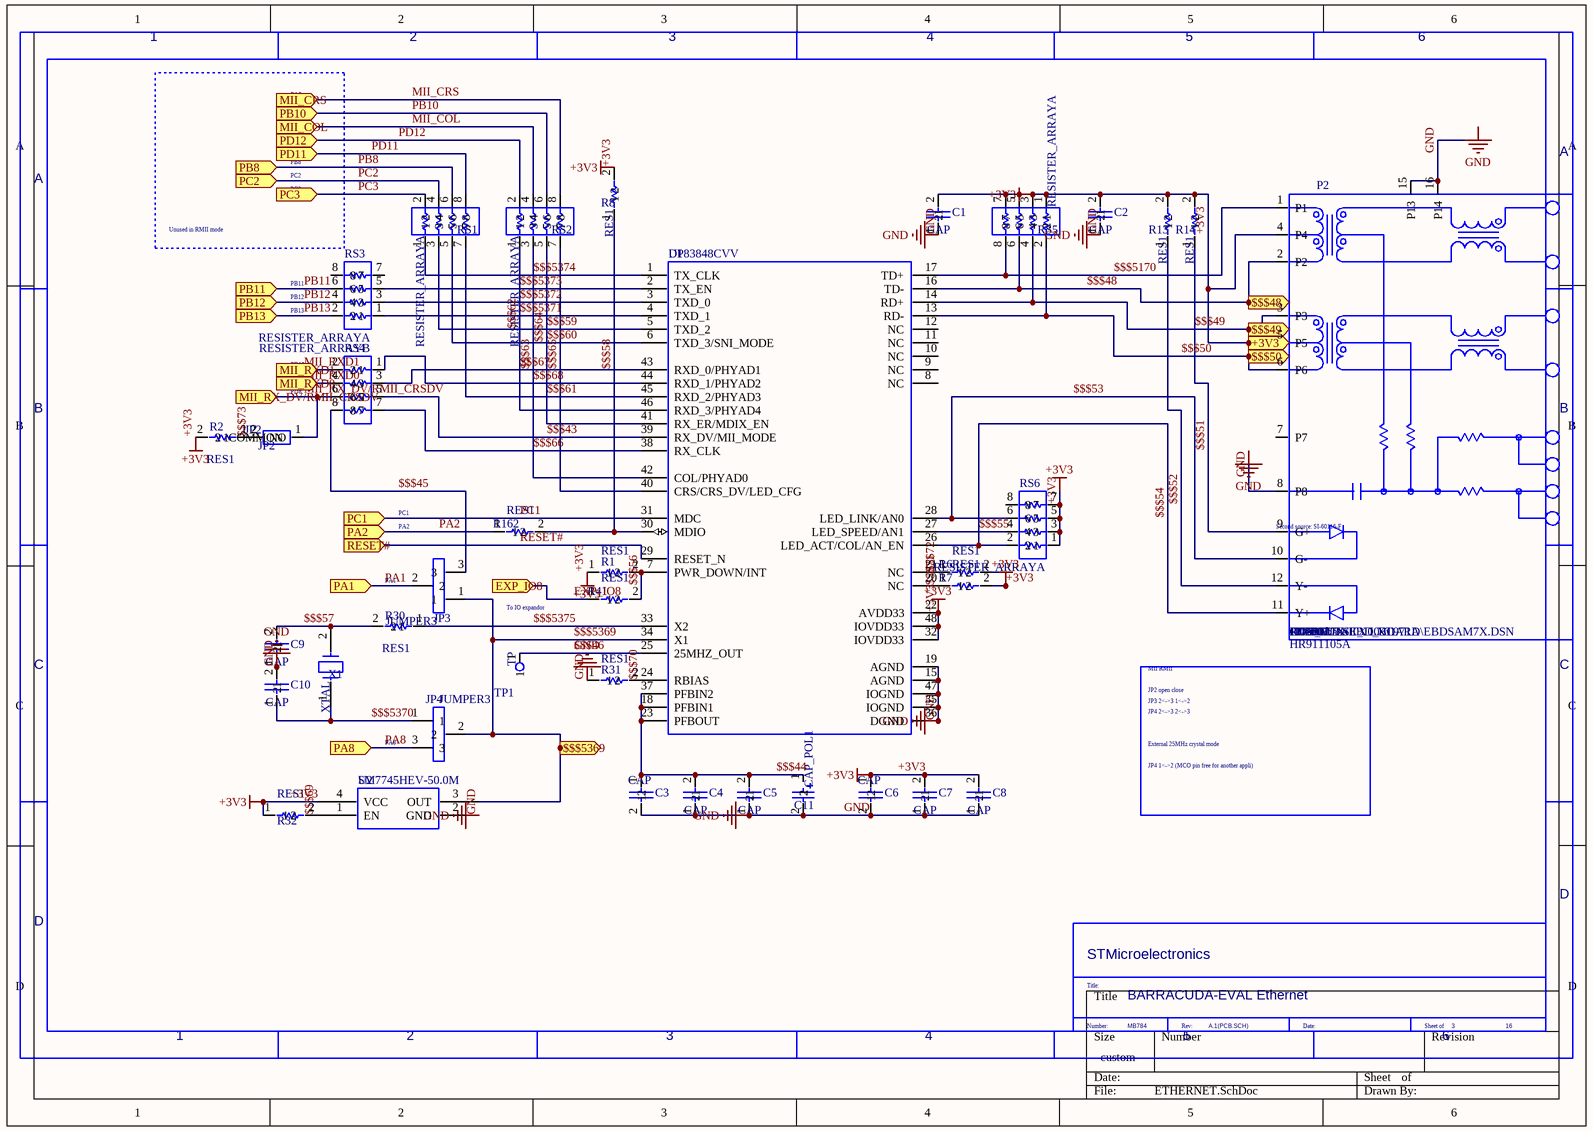
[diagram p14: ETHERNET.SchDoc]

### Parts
C1  CAP
C2  CAP
C3  CAP
C4  CAP
C5  CAP
C6  CAP
C7  CAP
C8  CAP
C9  CAP
C10  CAP
C11  CAP_POL1
JP2  JP2
JP3  JUMPER3
JP4  JUMPER3
P2  13F-60LDNL  VAL: HR911105A  Source Path: G:\SAM7X\EBD_BOARD\EBDSAM7X.DSN  DEV: CON_PULSE_J00-61  FAB: PULSE  BOI: RJ45  DESIG: 10/100 base TX LXT971A  REF: J00-0061
R1  RES1
R2  RES1
R6  RES1
R7  RES1
R8  RES1
R13  RES1
R14  RES1
R30  RES1
R31  RES1
R32  RES1
R41  RES1
R162  RES1
RS1  RESISTER_ARRAYA
RS2  RESISTER_ARRAYA
RS3  RESISTER_ARRAYA
RS4  RESISTER_ARRAYB
RS5  RESISTER_ARRAYA
RS6  RESISTER_ARRAYA
TP1  TP
U1  DP83848CVV
U2  SM7745HEV-50.0M
X1  XTAL

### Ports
$$$48, $$$49, $$$50, $$$5369, +3V3, EXP_IO8, MII_COL, MII_CRS, MII_RX_DV/RMII_CRSDV, MII_RXD0, MII_RXD1, PA1, PA2, PA8, PB8, PB10, PB11, PB12, PB13, PC1, PC2, PC3, PD11, PD12, RESET#

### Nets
+3V3: C1.2 C2.2 C6.1 C7.2 C8.2 P2.4(P4) P2.5(P5) R1.1 R2.2 R6.2 R7.2 R8.2 R13.2 R14.2 R32.1 RS5.1 RS5.3 RS5.5 RS5.7 RS6.1 RS6.3 RS6.5 RS6.7 U1.22(AVDD33) U1.32(IOVDD33) U1.48(IOVDD33) U2.4(VCC) ; port +3V3
GND: C1.1 C2.1 C3.2 C4.1 C5.1 C6.2 C7.1 C8.1 C9.1 C10.2 C11.2 P2.8(P8) P2.15(P13) P2.16(P14) R31.1 U1.15(AGND) U1.19(AGND) U1.35(IOGND) U1.36(DGND) U1.47(IOGND) U2.2(GND)  [project net $$$275]
$$$43: RS4.5 U1.39(RX_DV/MII_MODE)
$$$44: C3.1 C4.2 C5.2 C11.1 U1.18(PFBIN1) U1.23(PFBOUT) U1.37(PFBIN2)
$$$45: JP3.3 RS4.8
$$$46: TP1.1 U1.25(25MHZ_OUT)
$$$48: P2.2(P2) RS5.6 U1.16(TD-) ; port $$$48
$$$49: P2.3(P3) P2.9(G+) R14.1 RS5.4 U1.14(RD+) ; port $$$49  [also labelled $$$51]
$$$50: P2.6(P6) RS5.2 U1.13(RD-) ; port $$$50
$$$52: P2.12(Y-) R13.1
$$$53: P2.10(G-) RS6.6 U1.28(LED_LINK/AN0)
$$$54: P2.11(Y+) RS6.2 RS6.4 U1.26(LED_ACT/COL/AN_EN) U1.27(LED_SPEED/AN1)  [also labelled $$$55]
$$$56: R1.2 R41.2 U1.7(PWR_DOWN/INT)
$$$57: C9.2 R30.2 X1.2
$$$69: R32.2 U2.1(EN)
$$$70: R31.2 U1.24(RBIAS)
$$$71: R7.1 U1.20(NC)
$$$72: R6.1 U1.21(NC)
$$$73: JP2.2(NO) R2.1
$$$5170: P2.1(P1) RS5.8 U1.17(TD+)
$$$5369: JP3.1 JP4.2 U1.34(X1) U2.3(OUT) ; port $$$5369
$$$5370: C10.1 JP4.1 X1.1
$$$5371: R8.1 R162.2 RS1.1 RS1.3 RS1.5 RS1.7 RS2.1 RS2.3 RS2.5 RS2.7 RS3.1 RS3.3 RS3.5 RS4.1 RS4.3 RS4.7 U1.1(TX_CLK) U1.2(TX_EN) U1.3(TXD_0) U1.4(TXD_1) U1.5(TXD_2) U1.6(TXD_3/SNI_MODE) U1.30(MDIO) U1.38(RX_CLK) U1.40(CRS/CRS_DV/LED_CFG) U1.41(RX_ER/MDIX_EN) U1.42(COL/PHYAD0) U1.43(RXD_0/PHYAD1) U1.44(RXD_1/PHYAD2) U1.45(RXD_2/PHYAD3) U1.46(RXD_3/PHYAD4)  [also labelled $$$5372, $$$5373, $$$5374, $$$58, $$$59, $$$60, $$$61, $$$62, $$$63, $$$64, $$$65, $$$66, $$$67, $$$68]
$$$5375: R30.1 U1.33(X2)
EXP_IO8: R41.1 ; port EXP_IO8  [project net EXP_IO7]
MII_COL: RS2.4 ; port MII_COL
MII_CRS: RS2.8 ; port MII_CRS
MII_RX_DV/RMII_CRSDV: JP2.1(COMMON) RS4.6 ; port MII_RX_DV/RMII_CRSDV
MII_RXD0: RS4.4 ; port MII_RXD0
MII_RXD1: RS4.2 ; port MII_RXD1
PA1: JP3.2 ; port PA1
PA2: R162.1 ; port PA2
PA8: JP4.3 ; port PA8
PB8: RS1.6 ; port PB8
PB10: RS2.6 ; port PB10
PB11: RS3.6 ; port PB11
PB12: RS3.4 ; port PB12
PB13: RS3.2 ; port PB13
PC1: U1.31(MDC) ; port PC1
PC2: RS1.4 ; port PC2
PC3: RS1.2 ; port PC3
PD11: RS1.8 ; port PD11
PD12: RS2.2 ; port PD12
RESET#: U1.29(RESET_N) ; port RESET#

Not connected (* = marked no-connect by the designer): P2 7(P7); RS3 7 8; RS6 8; U1 8(NC) 9(NC) 10(NC) 11(NC) 12(NC)

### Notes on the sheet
- 1
- 2
- 3
- 4
- 5
- 6
- PA0
- PA3
- PB10
- PD12
- A
- PD11
- PB8
- PC2
- PC3
- Unused in RMII mode
- (near RS3) PB13
- (near RS3) PB12
- (near RS3) PB11
- PD8
- PD10
- PD9
- B
- (near JP3) PA2
- PC1
- (near P2) Second source: SI-60116-F
- PA1
- To IO expandor
- C
- MII RMII
- PA8
- External 25MHz crystal mode
- JP4 2<->3 2<->3
- JP3 2<->3 1<->2
- JP2 open close
- JP4 1<->2 (MCO pin free for another appli)
- D
- Title:
- STMicroelectronics
- BARRACUDA-EVAL Ethernet
- Number:
- MB784
- Rev:
- A.1(PCB.SCH)
- Date:
- Sheet of
- 16

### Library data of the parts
C1-C10 = CAP: Capacitor; PCB DECAL: 0603
C11 = CAP_POL1: as C51 on sheet POWER
JP2 = JP2: PCB DECAL: SIP2
JP3 JP4 = JUMPER3: PCB DECAL: SIP3
P2 = 13F-60LDNL: Value: HR911105A; PCB DECAL: 13F-60LDNLP
R1 R2 R6-R8 R13 R14 R30-R32 R41 R162 = RES1: as R87 on sheet EXTENSIONCONNECTOR
RS4 = RESISTER_ARRAYB: PCB DECAL: RES-4B
U1 = DP83848CVV: PCB DECAL: LQFP48
X1 = XTAL: Crystal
